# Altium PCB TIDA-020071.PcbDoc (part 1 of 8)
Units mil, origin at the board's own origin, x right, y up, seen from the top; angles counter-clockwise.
Board outline 5750 x 4050 mil, 6 copper layers (Top Layer, GND PLANE-1, SIGNAL LAYER, SIGNAL/POWER LAYER, GND PLANE-2, Bottom Layer), stack 59.616 mil thick; 776 components, 498 nets, 2205 pads, 871 vias.
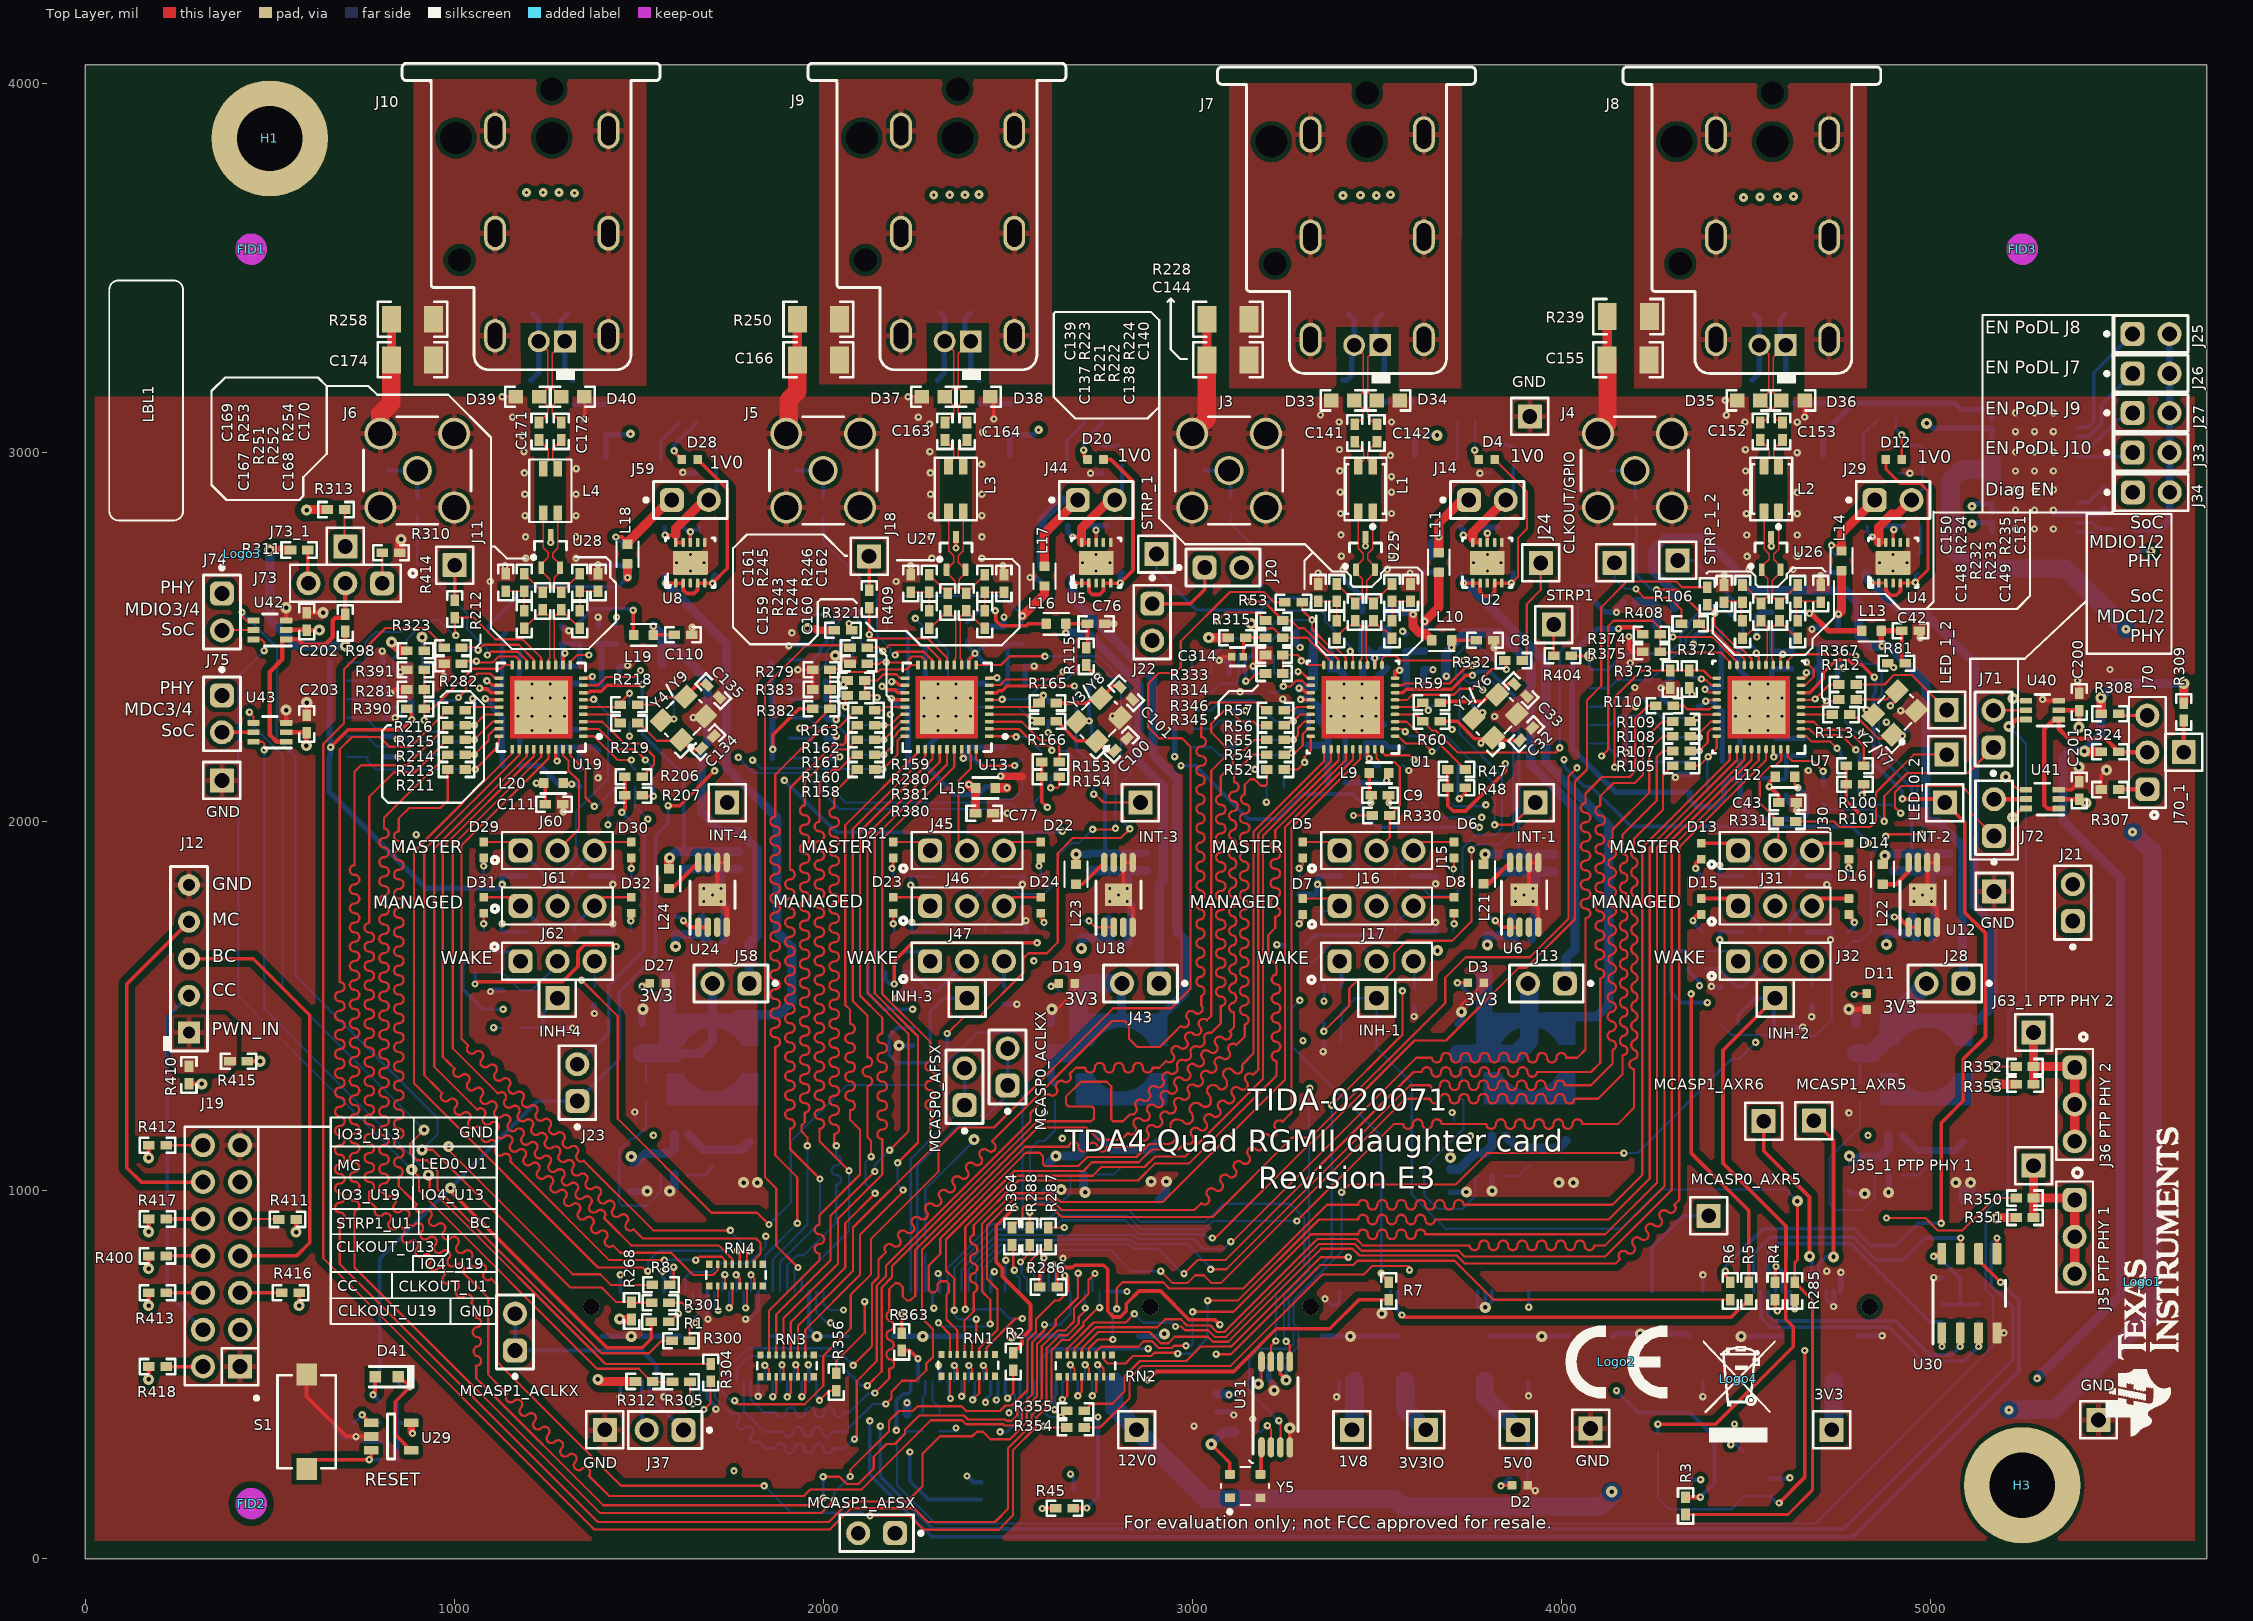
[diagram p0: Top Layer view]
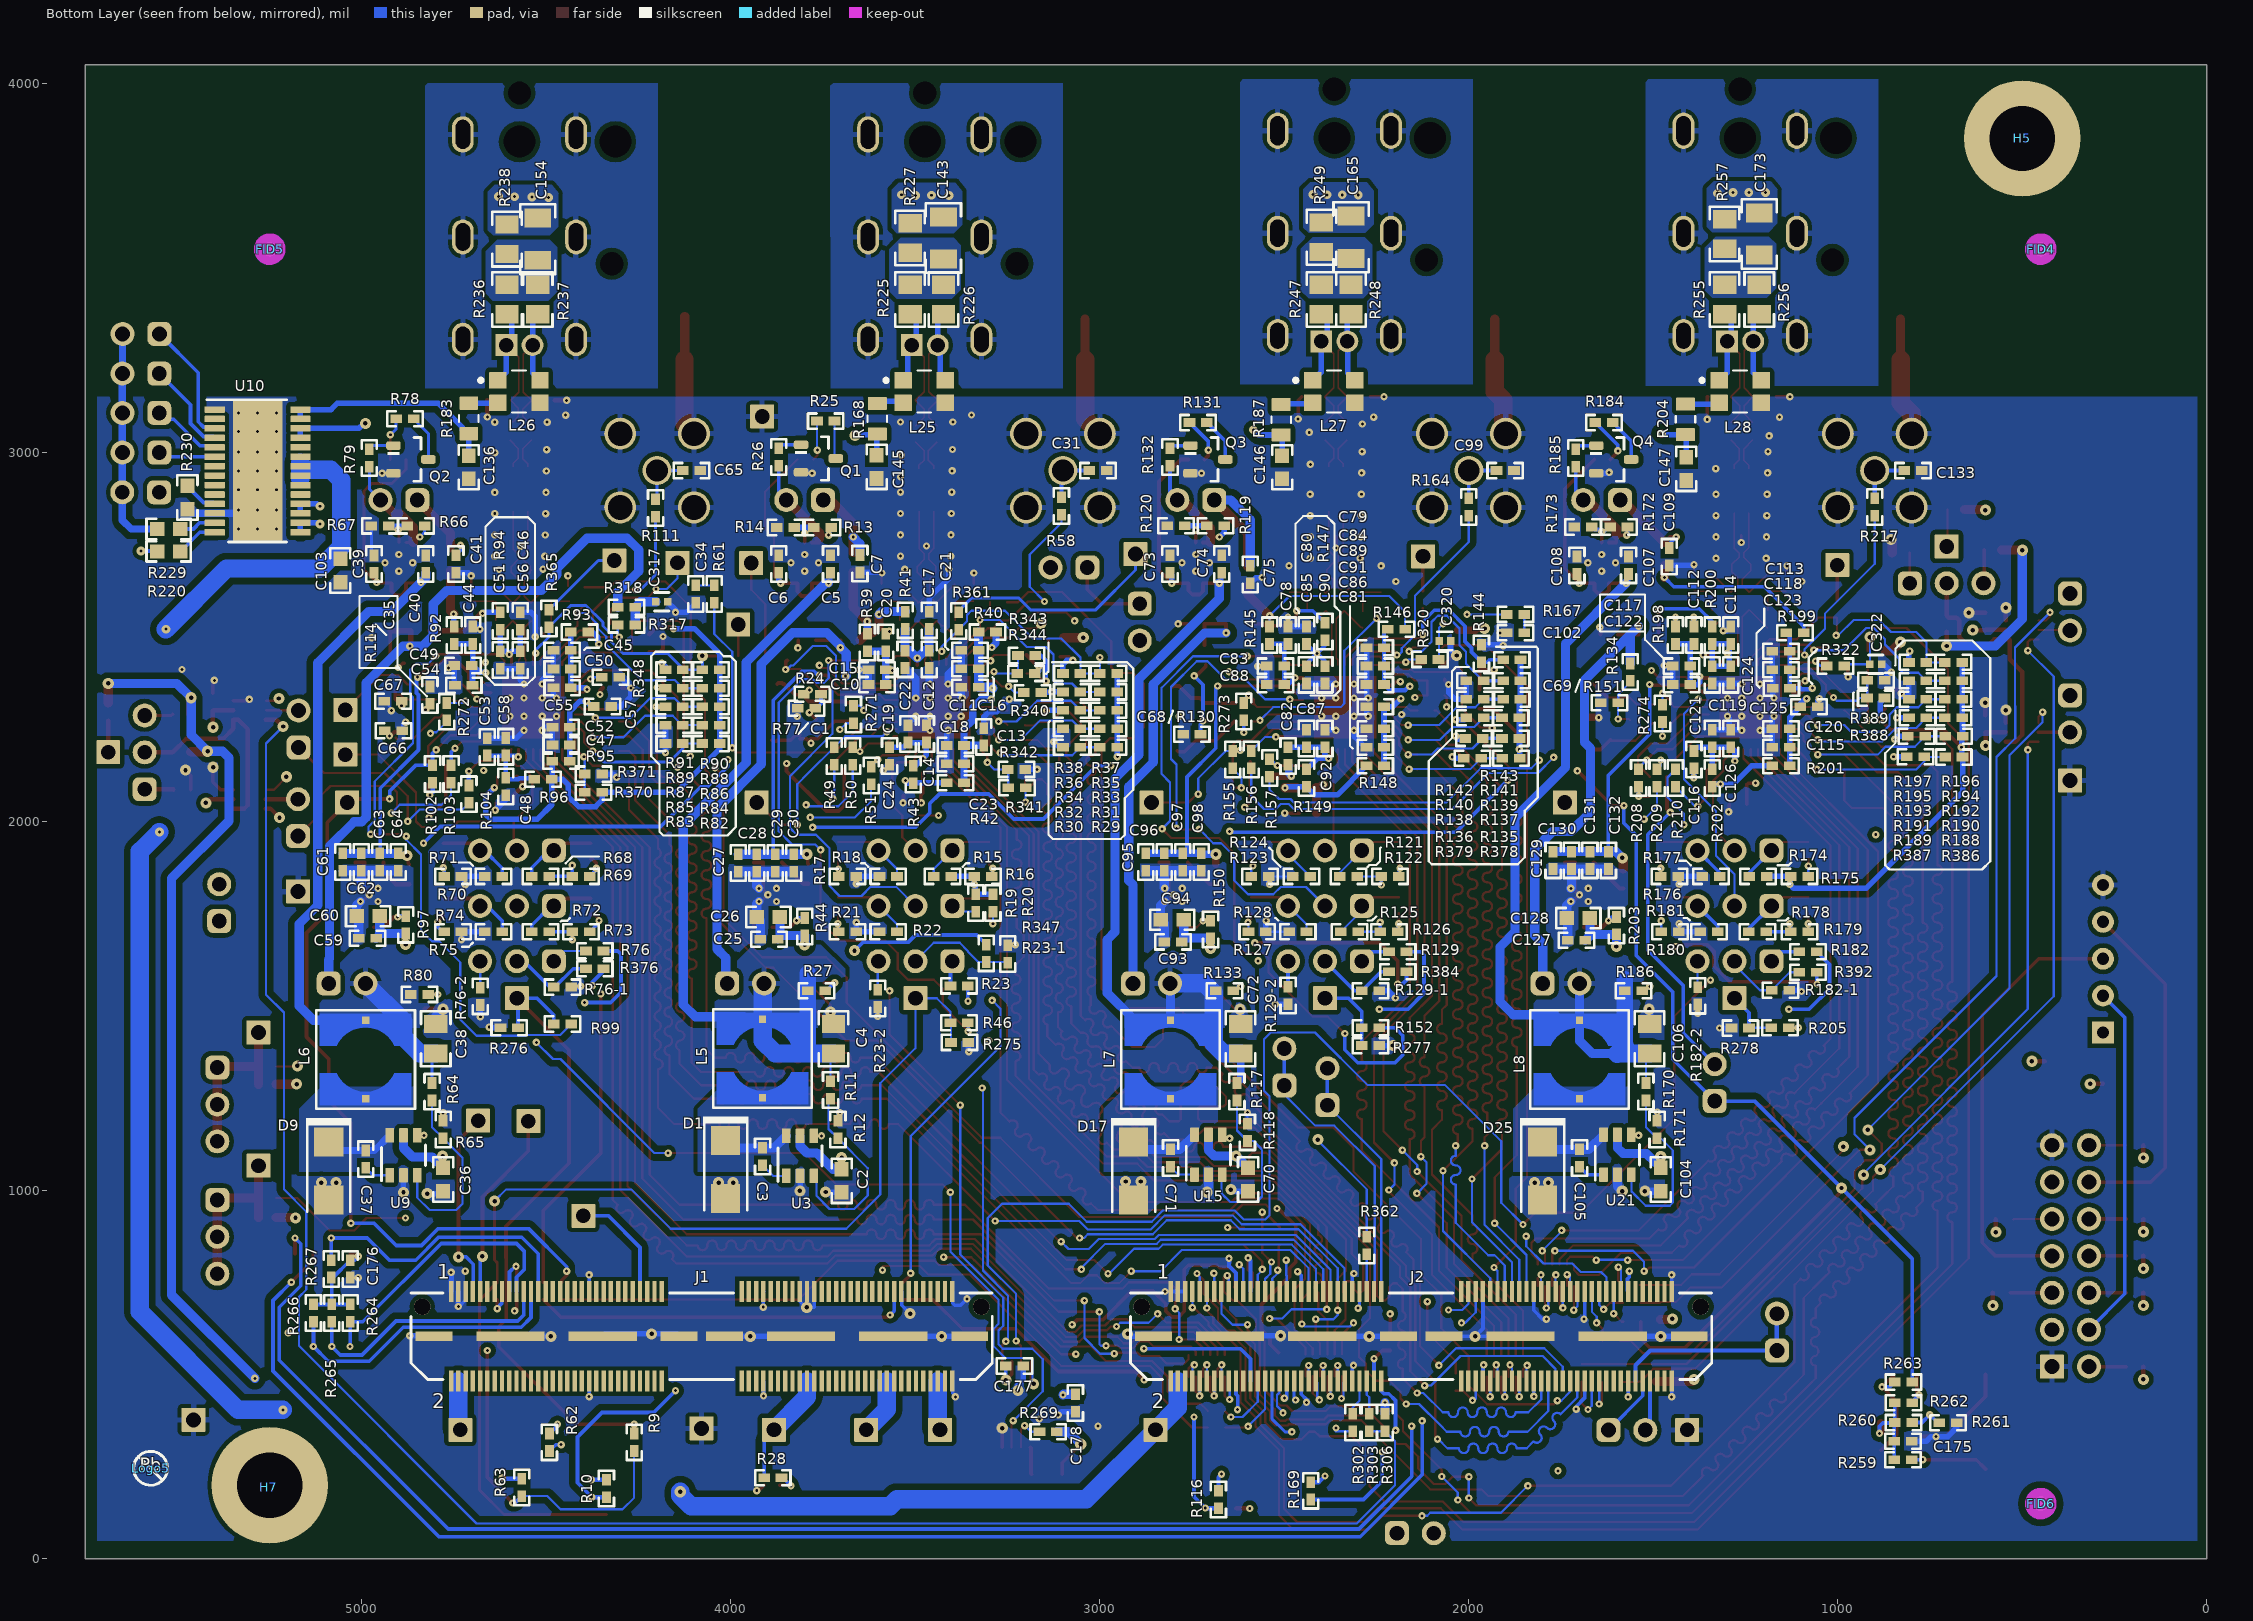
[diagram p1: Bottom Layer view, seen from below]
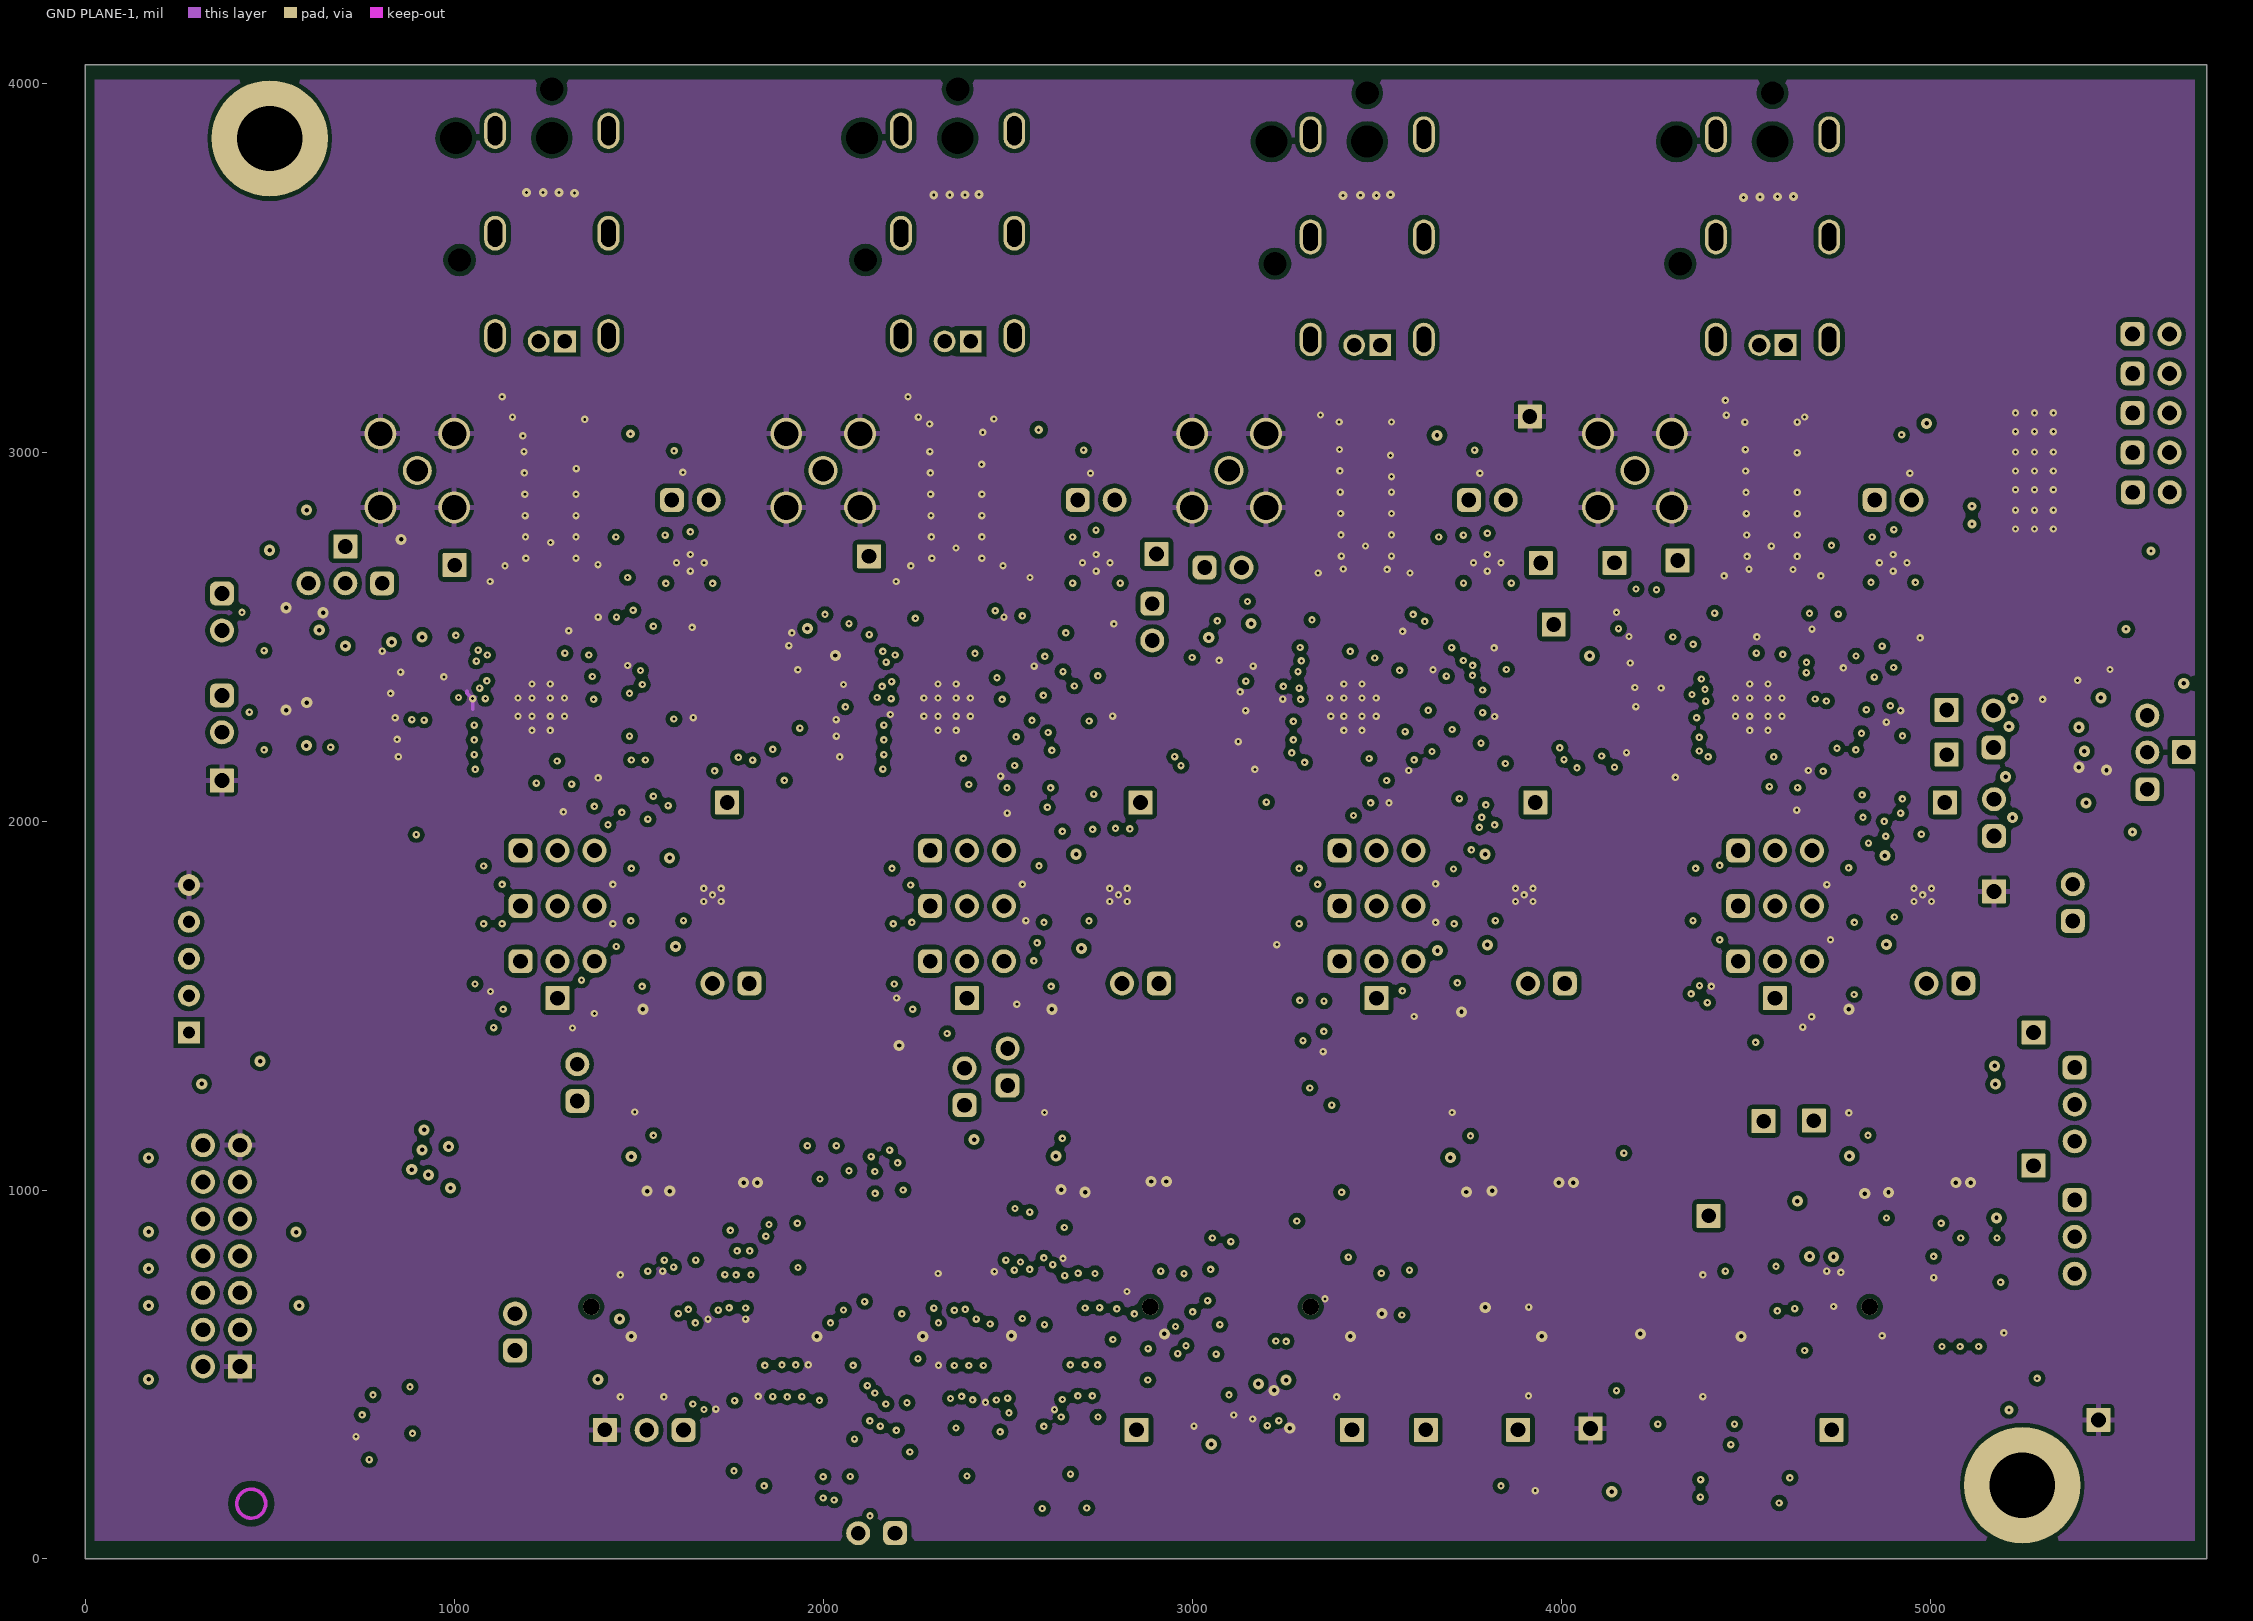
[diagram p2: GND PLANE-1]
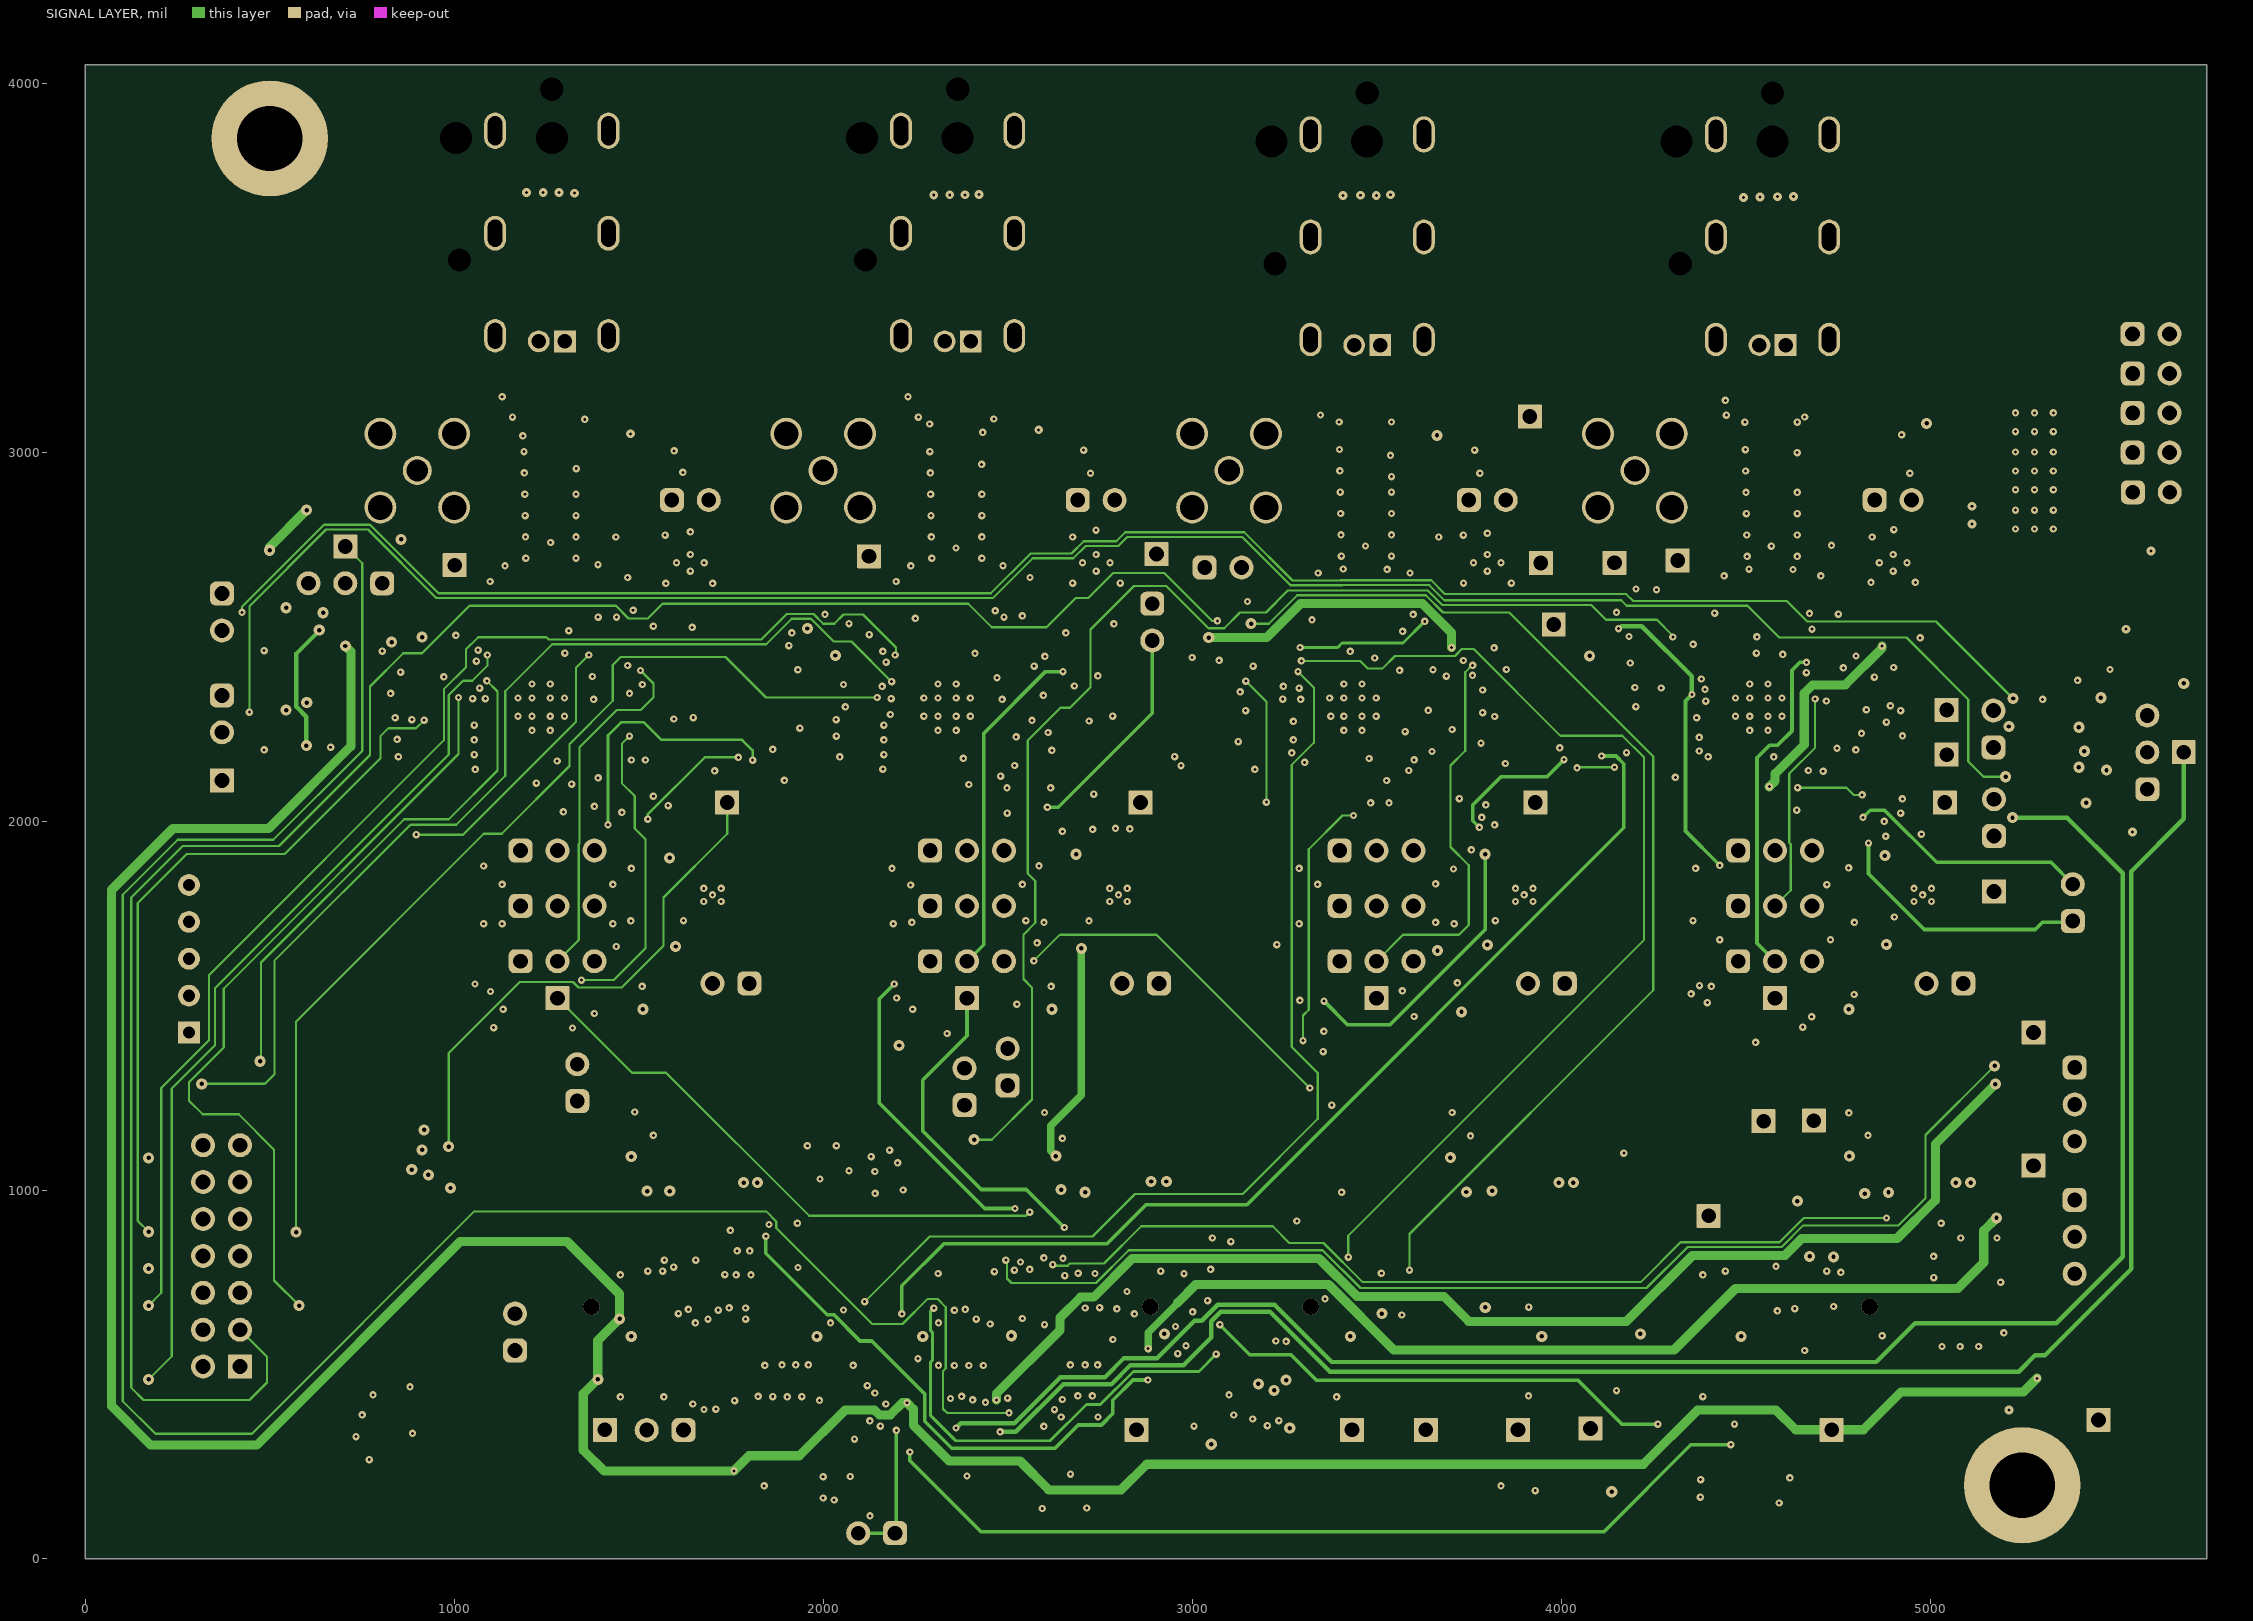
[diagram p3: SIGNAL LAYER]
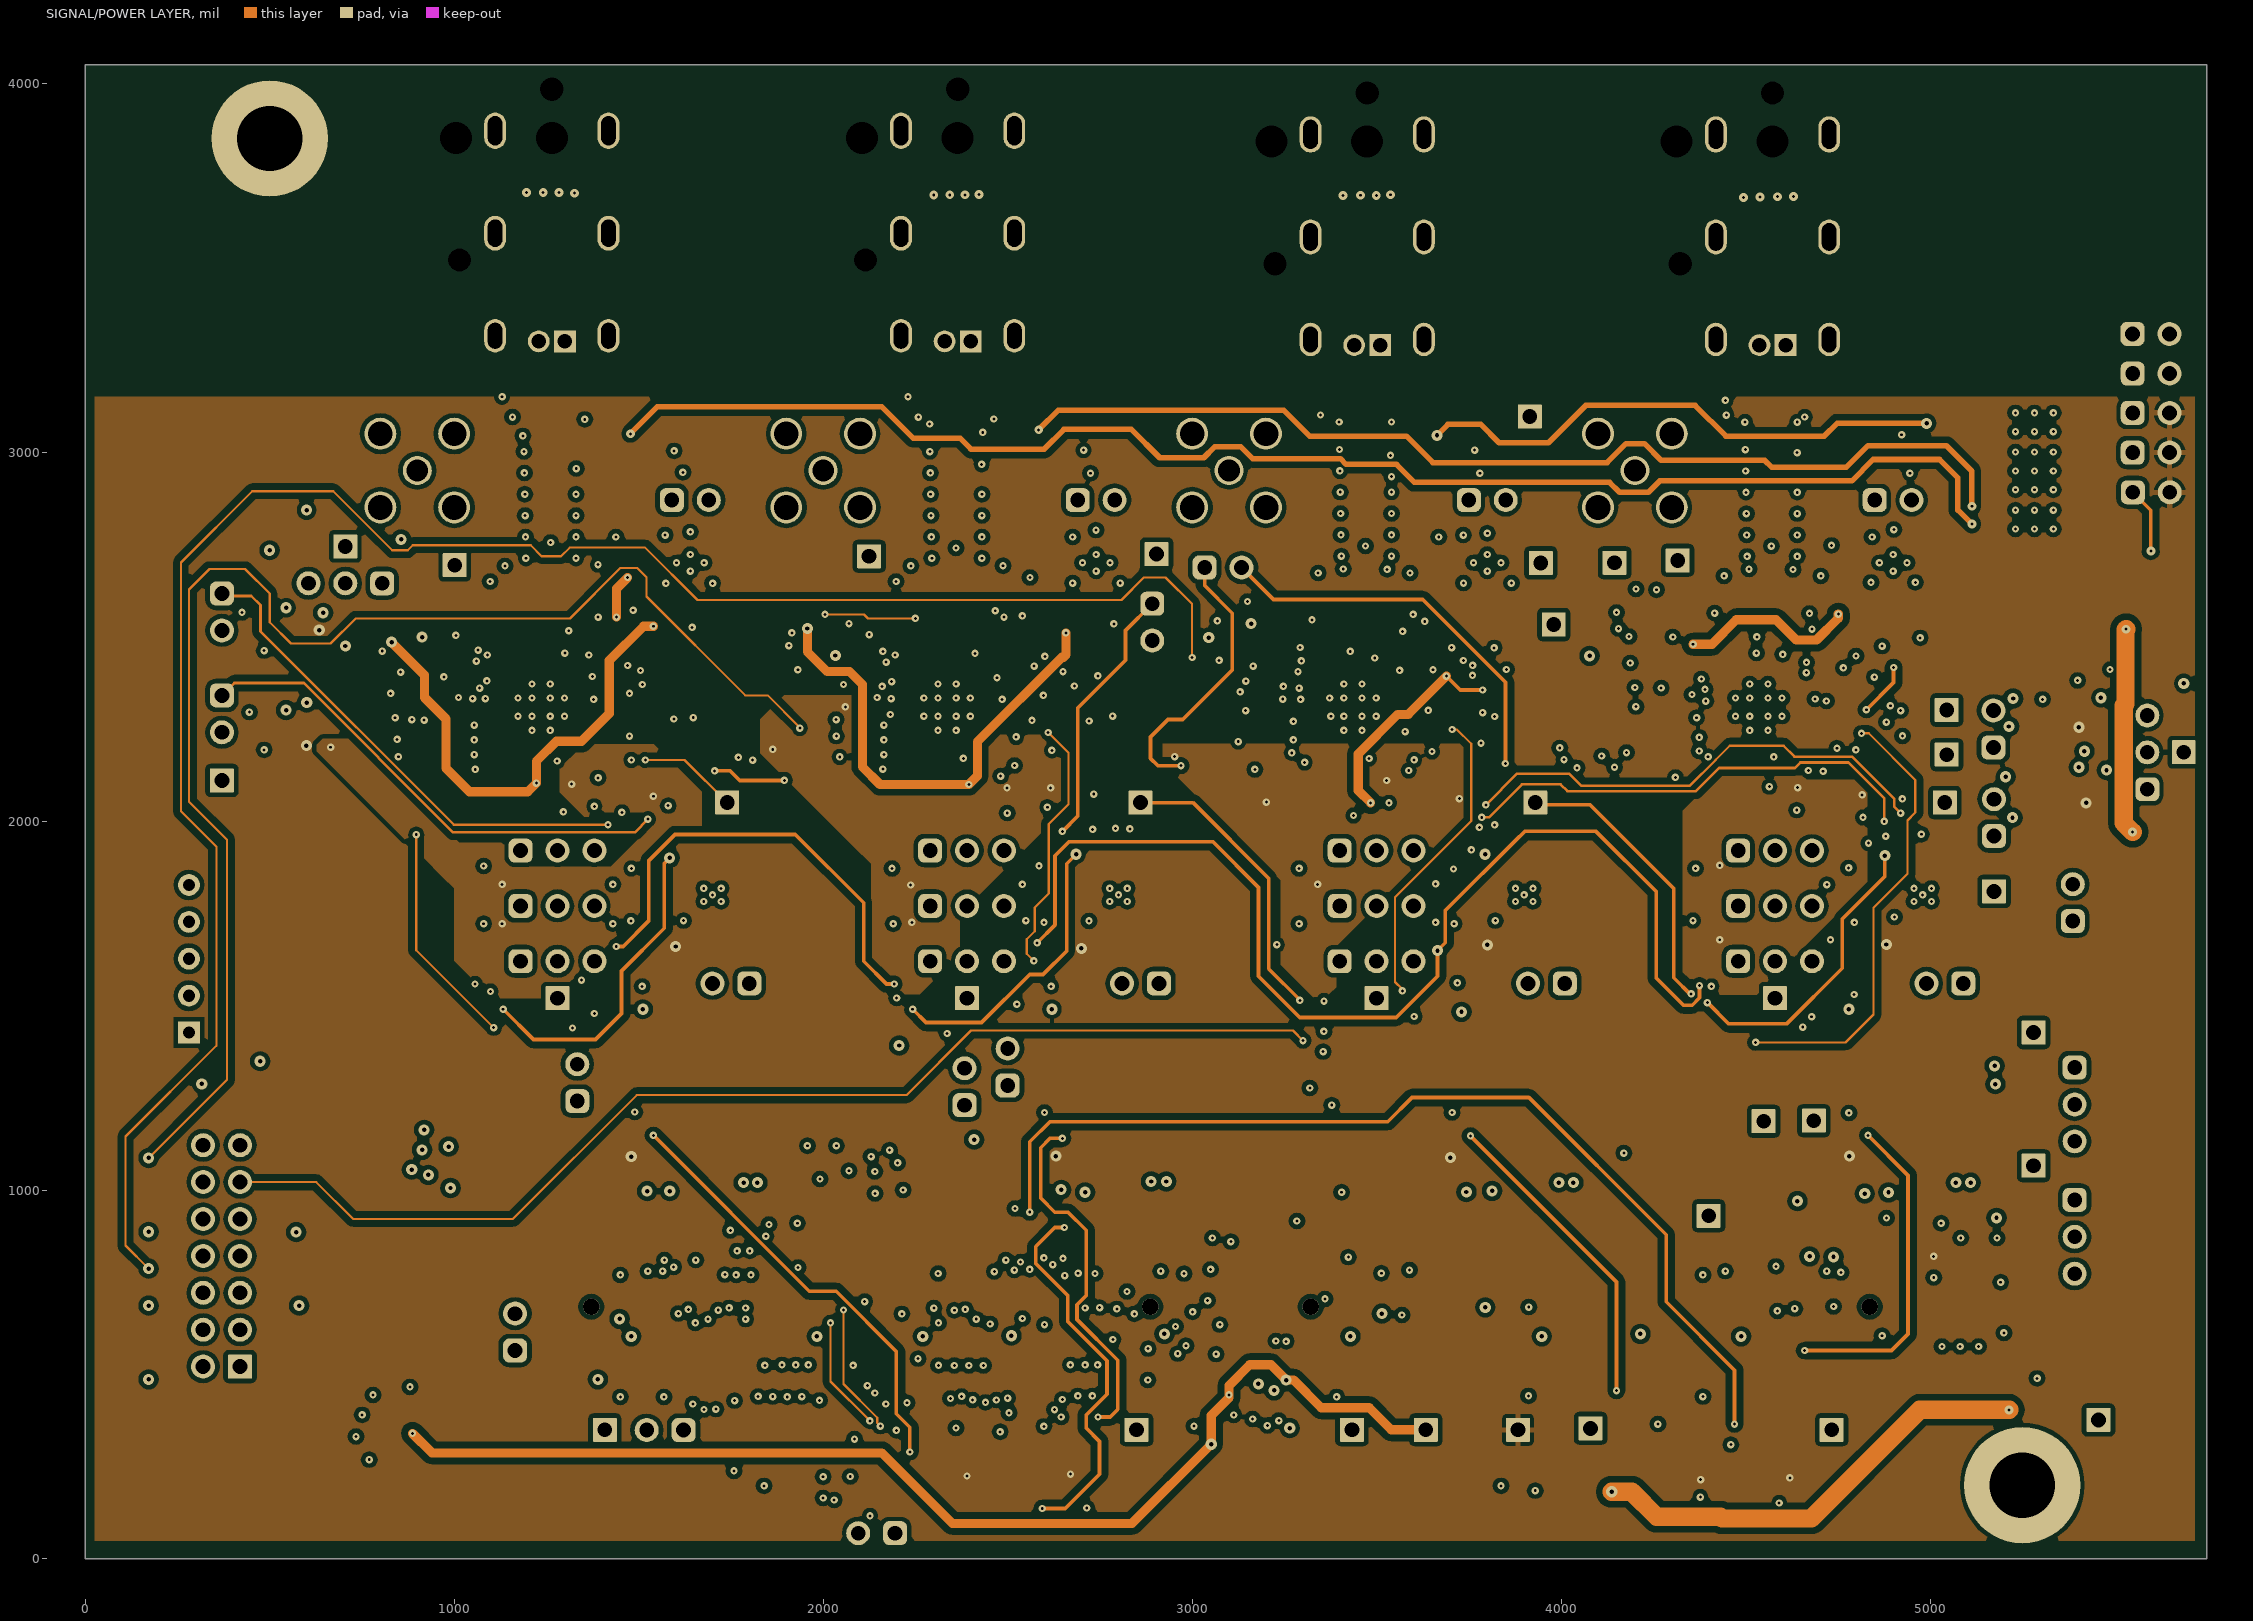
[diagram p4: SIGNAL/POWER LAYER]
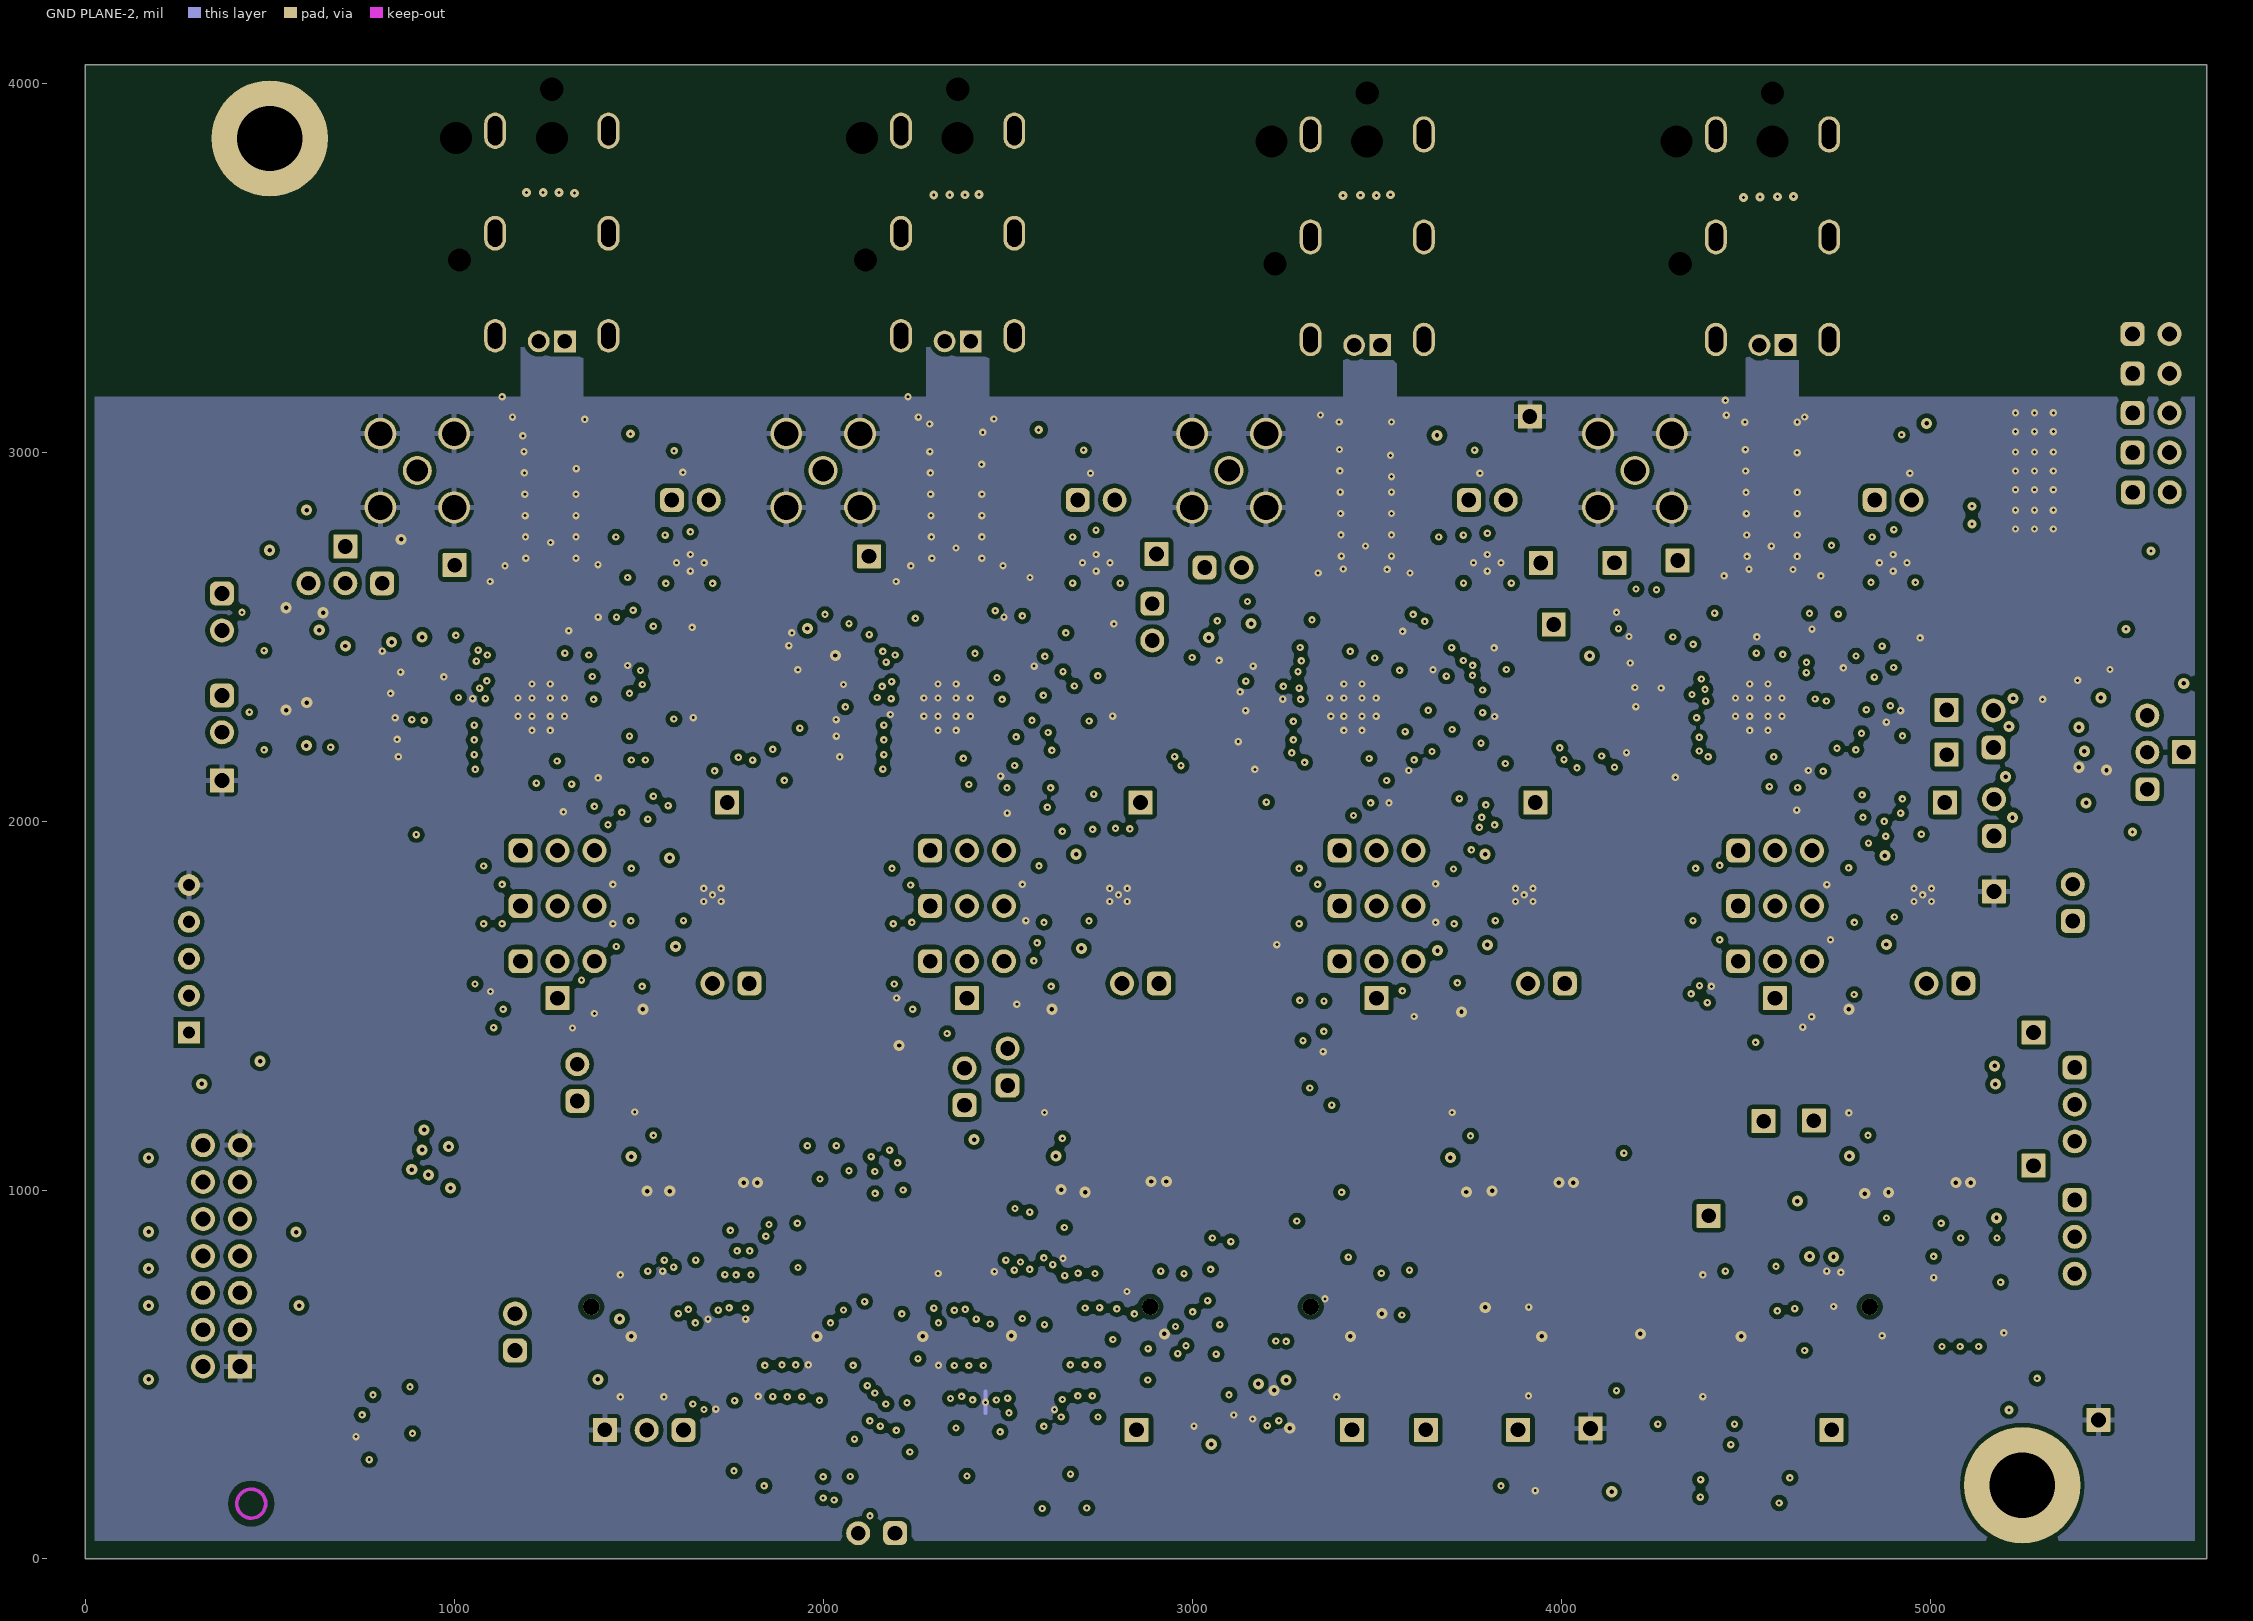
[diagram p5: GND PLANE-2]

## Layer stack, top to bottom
Top Solder: solder mask 0.4, Solder Resist, Dk 3.5
Top Layer: signal copper 1.4
Dielectric 1: prepreg 3.937, IT180A, Dk 4.1
GND PLANE-1: signal copper 1.4
Dielectric 2: core 5.906, IT180A, Dk 4.1
SIGNAL LAYER: signal copper 1.4
Dielectric 3: prepreg 31.496, IT180A, Dk 4.1
SIGNAL/POWER LAYER: signal copper 1.417
Dielectric 5: core 5.906, IT180A, Dk 4.1
GND PLANE-2: signal copper 1.417
Dielectric 4: prepreg 3.937, IT180A, Dk 4.1
Bottom Layer: signal copper 1.4
Bottom Solder: solder mask 0.4, Solder Resist, Dk 3.5

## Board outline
0,0 0,4050 5750,4050 5750,0

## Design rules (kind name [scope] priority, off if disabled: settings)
AcuteAngle [All] p1: minimum=4.50000000000000E+0001 checktracksonly=FALSE
AssemblyTestPointUsage [All] p1: valid=2
BoardOutlineClearance BoardOutlineClearance_MountingHoles [OnCopper and InComponentClass('Mounting Holes')] p1: gap=40 ignorepadtopadclearanceinfootprint=FALSE
BoardOutlineClearance BoardOutlineClearance_Poly [OnCopper and IsPoly] p2: gap=25 ignorepadtopadclearanceinfootprint=FALSE
BoardOutlineClearance [OnCopper and Not InComponentClass('Logo') and not InComponentClass('FiducialMark') and not InRegion(1000,500,4000,800) and not InPoly] p3: gap=75 ignorepadtopadclearanceinfootprint=FALSE except(30: SMDPad-OutlineEdge THPad-OutlineEdge THPad-CavityEdge THPad-CutoutEdge THPad-SplitBarrior THPad-SplitContinuation; 40: Track-OutlineEdge Track-CavityEdge Track-CutoutEdge Track-SplitBarrior Track-SplitContinuation Via-OutlineEdge Via-CavityEdge Via-CutoutEdge Via-SplitBarrior Via-SplitContinuation Fill-OutlineEdge Fill-CavityEdge Fill-CutoutEdge Fill-SplitBarrior Fill-SplitContinuation)
Clearance Clearance_Keepouts [((IsTrack Or IsArc) And Not InPoly) And IsFree and IsKeepOut vs ((IsTrack Or IsArc) And Not InPoly) And IsFree and IsKeepOut] p1: gap=0 ignorepadtopadclearanceinfootprint=FALSE
Clearance Clearance_Poly [InPolygon] p2: gap=12 ignorepadtopadclearanceinfootprint=FALSE except(18: Arc-Fill Arc-Poly Arc-Region Track-Fill Track-Poly Track-Region)
Clearance Clearance_FiducialMark [IsKeepOut and InComponentClass('FiducialMark') vs IsPad and InComponentClass('FiducialMark')] p3: gap=0 ignorepadtopadclearanceinfootprint=FALSE
Clearance [All] p4: gap=7 ignorepadtopadclearanceinfootprint=FALSE except(10: Arc-Hole Track-Hole Fill-Hole Poly-Hole Region-Hole)
ComponentClearance ComponentClearance_MountingHoles_FiducialMarks [InComponentClass('Mounting Holes') vs InComponentClass('FiducialMark')] p1: gap=50 collisioncheckmode=3 verticalgap=10 showdistances=FALSE
ComponentClearance ComponentClearance_Shunt [InComponentClass('Header') vs InComponentClass('Shunt')] p2: gap=0 collisioncheckmode=3 verticalgap=0 showdistances=FALSE
ComponentClearance ComponentClearance_Logo [InComponentClass('Logo')] p3: gap=50 collisioncheckmode=3 verticalgap=10 showdistances=FALSE
ComponentClearance ComponentClearance_ScrewToNut [(HasFootprint('NY PMS 440 0025 PH')) vs (HasFootprint('Keystone_1902C'))] p4: gap=0 collisioncheckmode=3 verticalgap=0 showdistances=FALSE
ComponentClearance ComponentClearance_MountingHoles [InComponentClass('Mounting Holes')] p5: gap=250 collisioncheckmode=3 verticalgap=100000 showdistances=FALSE
ComponentClearance ComponentClearance_SmallPassives [HasFootprint('0201*') or HasFootprint('0402*') or HasFootprint('0508') or HasFootprint('0603*') or HasFootprint('0612') or HasFootprint('0805*') or HasFootprint('0815*') or HasFootprint('0830*') or HasFootprint('1206*') or HasFootprint('1210*') or HasFootprint('1808*') or HasFootprint('1812*') or HasFootprint('1825*') or HasFootprint('2010*') or HasFootprint('2220*') or HasFootprint('2225*') or HasFootprint('2512*') or HasFootprint('2728*') or HasFootprint('3518*') vs HasFootprint('0201*') or HasFootprint('0402*') or HasFootprint('0508') or HasFootprint('0603*') or HasFootprint('0612') or HasFootprint('0805*') or HasFootprint('0815*') or HasFootprint('0830*') or HasFootprint('1206*') or HasFootprint('1210*') or HasFootprint('1808*') or HasFootprint('1812*') or HasFootprint('1825*') or HasFootprint('2010*') or HasFootprint('2220*') or HasFootprint('2225*') or HasFootprint('2512*') or HasFootprint('2728*') or HasFootprint('3518*')] p6: gap=14.96 collisioncheckmode=3 verticalgap=10 showdistances=FALSE
ComponentClearance ComponentClearance_THtoSMT [IsThruComponent vs IsSMTComponent] p7: gap=5 collisioncheckmode=3 verticalgap=5 showdistances=FALSE
ComponentClearance ComponentClearance_THtoTH [IsThruComponent vs IsThruComponent] p8: gap=4 collisioncheckmode=3 verticalgap=4 showdistances=FALSE
ComponentClearance [All] p9: gap=5 collisioncheckmode=3 verticalgap=5 showdistances=FALSE
DiffPairsRouting TRD [InDifferentialPairClass('TRD4')] p1: maxlimit=8 minlimit=8 mostfreqgap=8 toplayer_minwidth=4 toplayer_maxwidth=4 toplayer_prefwidth=4 midlayer1_minwidth=4 midlayer1_maxwidth=4 midlayer1_prefwidth=4 midlayer2_minwidth=4 midlayer2_maxwidth=4 midlayer2_prefwidth=4 midlayer3_minwidth=4 midlayer3_maxwidth=4 midlayer3_prefwidth=4 midlayer4_minwidth=4 midlayer4_maxwidth=4 midlayer4_prefwidth=4 bottomlayer_minwidth=4 bottomlayer_maxwidth=4 bottomlayer_prefwidth=4 maxuncoupledlength=500
DiffPairsRouting [All] p2: maxlimit=100 minlimit=8 mostfreqgap=10 toplayer_maxgap=20 toplayer_prefgap=8 toplayer_minwidth=4 toplayer_maxwidth=10 toplayer_prefwidth=4 midlayer1_mingap=10 midlayer1_minwidth=8 midlayer1_maxwidth=12 midlayer1_prefwidth=10 midlayer2_mingap=10 midlayer2_minwidth=8 midlayer2_maxwidth=12 midlayer2_prefwidth=10 midlayer3_mingap=10 midlayer3_minwidth=15 midlayer3_maxwidth=15 midlayer3_prefwidth=15 midlayer4_mingap=10 midlayer4_minwidth=15 midlayer4_maxwidth=15 midlayer4_prefwidth=15 bottomlayer_maxgap=20 bottomlayer_prefgap=8 bottomlayer_minwidth=4 bottomlayer_maxwidth=10 bottomlayer_prefwidth=4 maxuncoupledlength=1000
FabricationTestPointUsage TestPointUsage [All] p1: valid=2 allowmultiple=FALSE
FabricationTestpoint Testpoint [All] p1: side=3 testpointundercomponent=TRUE minsize=40 maxsize=100 preferedsize=60 minholesize=0 maxholesize=40 preferedholesize=32 testpointgrid=1 allowsidetop=TRUE allowsidebottom=TRUE usegrid=TRUE gridtolerance=0.01
FanoutControl Fanout_LCC [IsLCC] p1: bgadir=Out bgaviamode=Centered fanoutstyle=Auto fanoutdirection=Alternating viagrid=1 // Fanout_LCC (Default Rule)
FanoutControl Fanout_BGA [IsBGA] p2: bgadir=Out bgaviamode=Centered fanoutstyle=Auto fanoutdirection=Alternating viagrid=1 // Fanout_BGA (Default Rule)
FanoutControl Fanout_Default [All] p4: bgadir=Out bgaviamode=Centered fanoutstyle=Auto fanoutdirection=Alternating viagrid=1 // Fanout_Default (Default Rule)
FanoutControl Fanout_Small [(CompPinCount < 5)] p5: bgadir=Out bgaviamode=Centered fanoutstyle=Auto fanoutdirection=OutThenIn viagrid=1 // Fanout_Small (Default Rule)
HoleSize [All] p1: absolutevalues=TRUE maxlimit=251 minlimit=7.87 maxpercent=80.000 minpercent=20.000
MinimumAnnularRing MinimumAnnularRing_ThermalPadVias [IsVia and InAnyComponent] p1: minimumring=5.91
MinimumAnnularRing [All] p2: minimumring=5
MinimumSolderMaskSliver MinimumSolderMaskSliver_Logo [InComponentClass('Logo') vs InComponentClass('Logo')] p1: minsoldermaskwidth=0.7
MinimumSolderMaskSliver [All] p2: minsoldermaskwidth=3.7
PlaneClearance [All] p1: clearance=12
PlaneConnect [All] p1: planeconnectstyle=Direct reliefexpansion=10 reliefentries=4 reliefconductorwidth=10 reliefairgap=10
PolygonConnect PolygonConnect_1 [All] p1: thpad.connectstyle=Relief thpad.reliefconductorwidth=15 thpad.reliefentries=4 thpad.polygonreliefangle="90 Angle" thpad.airgapwidth=10 smdpad.connectstyle=Direct smdpad.reliefconductorwidth=10 smdpad.reliefentries=4 smdpad.polygonreliefangle="90 Angle" smdpad.airgapwidth=10 via.connectstyle=Direct via.reliefconductorwidth=10 via.reliefentries=4 via.polygonreliefangle="90 Angle" via.airgapwidth=10
PolygonConnect [All] p2: connectstyle=Direct reliefconductorwidth=10 reliefentries=4 polygonreliefangle="45 Angle" airgapwidth=10
RoutingVias ThermalPadVias [IsVia and InAnyComponent] p1: holewidth=7.87 width=19.68 viastyle="Through Hole" minholewidth=7.87 minwidth=19.68 maxholewidth=20 maxwidth=50
RoutingVias [All] p2: holewidth=12 width=30 viastyle="Through Hole" minholewidth=6 minwidth=18 maxholewidth=20 maxwidth=50
SilkToBoardRegionClearance [Not ((IsComment or IsDesignator) And (Hide <> 'False')) and not InRegion(1000,500,4000,800)] p1:
SilkToSilkClearance SilkToSilkClearance_Pb-FreeLogo [(HasFootprint('Pb-Free_Overlay_Medium') OR HasFootprint('Pb-Free_Overlay_Small')) vs (HasFootprint('Pb-Free_Overlay_Medium') OR HasFootprint('Pb-Free_Overlay_Small'))] p1: silktosilkclearance=0
SilkToSilkClearance [All] p2: silktosilkclearance=4
SilkToSolderMaskClearance SilkToComponentPadClearance [All] p1: minsilkscreentomaskgap=0 clearancetoexposedcopper=TRUE
SilkToSolderMaskClearance "Silk to Solder Mask Opening" [All] p2: minsilkscreentomaskgap=1 clearancetoexposedcopper=FALSE
SolderMaskExpansion [All] p1: expansion=1.97 istentingtop=FALSE
SupplyNets "Schematic Supply Nets_33" [InNet('+3V3-3')] p1: voltage=0.000
SupplyNets "Schematic Supply Nets_32" [InNet('+1V0_REG-4')] p2: voltage=0.000
SupplyNets "Schematic Supply Nets_31" [InNet('GND720-4')] p3: voltage=0.000
SupplyNets "Schematic Supply Nets_30" [InNet('Vpu-4')] p4: voltage=0.000
SupplyNets "Schematic Supply Nets_29" [InNet('+1V0-3')] p5: voltage=0.000
SupplyNets "Schematic Supply Nets_28" [InNet('+3V3_REG-4')] p6: voltage=0.000
SupplyNets "Schematic Supply Nets_27" [InNet('+3V3-4')] p7: voltage=0.000
SupplyNets "Schematic Supply Nets_26" [InNet('+3V3_REG-2')] p8: voltage=0.000
SupplyNets "Schematic Supply Nets_25" [InNet('3V3')] p9: voltage=0.000
SupplyNets "Schematic Supply Nets_24" [InNet('+1V1_REG-2')] p10: voltage=0.000
SupplyNets "Schematic Supply Nets_23" [InNet('GND')] p11: voltage=0.000
SupplyNets "Schematic Supply Nets_22" [InNet('1V8')] p12: voltage=0.000
SupplyNets "Schematic Supply Nets_21" [InNet('GND720-3')] p13: voltage=0.000
SupplyNets "Schematic Supply Nets_20" [InNet('GND720-1')] p14: voltage=0.000
SupplyNets "Schematic Supply Nets_19" [InNet('12V0')] p15: voltage=0.000
SupplyNets "Schematic Supply Nets_18" [InNet('+3V3-1')] p16: voltage=0.000
SupplyNets "Schematic Supply Nets_17" [InNet('+1V1_REG-1')] p17: voltage=0.000
SupplyNets "Schematic Supply Nets_16" [InNet('+1V1-2')] p18: voltage=0.000
SupplyNets "Schematic Supply Nets_15" [InNet('Vsleep3')] p19: voltage=0.000
SupplyNets "Schematic Supply Nets_14" [InNet('+1V1-1')] p20: voltage=0.000
SupplyNets "Schematic Supply Nets_13" [InNet('Vsleep4')] p21: voltage=0.000
SupplyNets "Schematic Supply Nets_12" [InNet('Vsleep1')] p22: voltage=0.000
SupplyNets "Schematic Supply Nets_11" [InNet('+1V0-4')] p23: voltage=0.000
SupplyNets "Schematic Supply Nets_10" [InNet('Vsleep2')] p24: voltage=0.000
SupplyNets "Schematic Supply Nets_9" [InNet('+3V3_REG-1')] p25: voltage=0.000
SupplyNets "Schematic Supply Nets_8" [InNet('3V3IO')] p26: voltage=0.000
SupplyNets "Schematic Supply Nets_7" [InNet('+1V0_REG-3')] p27: voltage=0.000
SupplyNets "Schematic Supply Nets_6" [InNet('5V0')] p28: voltage=0.000
SupplyNets "Schematic Supply Nets_5" [InNet('GND720-2')] p29: voltage=0.000
SupplyNets "Schematic Supply Nets_4" [InNet('+3V3_REG-3')] p30: voltage=0.000
SupplyNets "Schematic Supply Nets_3" [InNet('+3V3-2')] p31: voltage=0.000
SupplyNets "Schematic Supply Nets_2" [InNet('Vpu-2')] p32: voltage=0.000
SupplyNets "Schematic Supply Nets_1" [InNet('Vpu-3')] p33: voltage=0.000
SupplyNets "Schematic Supply Nets" [InNet('Vpu-1')] p34: voltage=0.000
Width rX1 [InNetClass('P0-R1-RD')and InNetClass('P0-R2-RD') and InNetClass('P1-R1-RD')and InNetClass('P1-R2-RD')and InNetClass('RX_D-1')] p1: maxlimit=11.4 minlimit=11.4 preferedwidth=11.4
Width [All] p2: maxlimit=100 minlimit=4 preferedwidth=10 checkconnectedcopper=TRUE
14 further rules are at their usual default settings.

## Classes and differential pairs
component class "AVB Headers": J11 J12 J18 J19 J24 R330 R332 R333 R400 R409 R410 R411 R412 R413 R414 R415 R416 R417 R418
component class MDIO_MUX: C200 C201 C202 C203 GND J70 J70_1 J71 J72 J73 J73_1 J74 J75 R98 R307 R308 R309 R310 R311 R313 R324 U40 U41 U42 U43
component class RESET: C175 D41 J20 J21 J22 J23 R259 R260 R261 R262 R263 S1 U29
component class Conn-TE-02: C167 C168 C169 C170 C171 C172 C173 C174 D39 D40 J10 L4 L28 R204 R251 R252 R253 R254 R255 R256 R257 R258 U28
component class Conn-TE-01: C159 C160 C161 C162 C163 C164 C165 C166 D37 D38 J9 L3 L27 R187 R243 R244 R245 R246 R247 R248 R249 R250 U27
component class Conn-Rb-02: C148 C149 C150 C151 C152 C153 C154 C155 D35 D36 J8 L2 L26 R183 R232 R233 R234 R235 R236 R237 R238 R239 U26
component class Conn-Rb-01: C137 C138 C139 C140 C141 C142 C143 C144 D33 D34 J7 L1 L25 R168 R221 R222 R223 R224 R225 R226 R227 R228 U25
component class "HSS and Memory": C103 C136 C145 C146 C147 C176 J25 J26 J27 J33 J34 R220 R229 R230 R264 R265 R266 R267 U10 U30
component class Header: 1V8 3V3 3V3IO 5V0 12V0 CLKOUT/GPIO GND INH-1 INH-2 INH-3 INH-4 INT-1 INT-2 INT-3 INT-4 J11 J12 J13 J14 J15 J16 J17 J18 J19 J20 J21 J22 J23 J24 J25 J26 J27 J28 J29 J30 J31 J32 J33 J34 "J35 PTP PHY 1" "J35_1 PTP PHY 1" "J36 PTP PHY 2" J37 J43 J44 J45 J46 J47 J58 J59 J60 J61 J62 "J63_1 PTP PHY 2" J70 J70_1 J71 J72 J73 J73_1 J74 J75 LED_0_2 LED_1_2 MCASP0_ACLKX MCASP0_AFSX MCASP0_AXR5 MCASP1_ACLKX MCASP1_AFSX MCASP1_AXR5 MCASP1_AXR6 STRP1 STRP_1 STRP_1_2
component class Connector: 1V8 3V3 3V3IO 5V0 12V0 GND J1 J2 "J35 PTP PHY 1" "J35_1 PTP PHY 1" "J36 PTP PHY 2" J37 "J63_1 PTP PHY 2" MCASP0_ACLKX MCASP0_AFSX MCASP0_AXR5 MCASP1_ACLKX MCASP1_AFSX MCASP1_AXR5 MCASP1_AXR6 R1 R2 R4 R5 R6 R7 R8 R268 R285 R286 R287 R288 R300 R301 R302 R303 R304 R305 R306 R312 R350 R351 R352 R353 R354 R355 R356 R362 R363 R364 RN1 RN2 RN3 RN4
component class CLOCK: C177 C178 R269 U31 Y5
component class 818-04: C69 C104 C105 C106 C107 C108 C109 C110 C111 C112 C113 C114 C115 C116 C117 C118 C119 C120 C121 C122 C123 C124 C125 C126 C127 C128 C129 C130 C131 C132 C133 C134 C135 C322 D25 D27 D28 D29 D30 D31 D32 INH-4 INT-4 J6 J58 J59 J60 J61 J62 L8 L18 L19 L20 L24 Q4 R62 R134 R151 R169 R170 R171 R172 R173 R174 R175 R176 R177 R178 R179 R180 R181 R182 R182-1 R182-2 R184 R185 R186 R188 R189 R190 R191 R192 R193 R194 R195 R196 R197 R198 R199 R200 R201 R202 R203 R205 R206 R207 R208 R209 R210 R211 R212 R213 R214 R215 R216 R217 R218 R219 R274 R278 R281 R282 R322 R323 R386 R387 R388 R389 R390 R391 R392 U8 U19 U21 U24 Y4 Y9
component class 818-03: C68 C70 C71 C72 C73 C74 C75 C76 C77 C78 C79 C80 C81 C82 C83 C84 C85 C86 C87 C88 C89 C90 C91 C92 C93 C94 C95 C96 C97 C98 C99 C100 C101 C102 C320 D17 D19 D20 D21 D22 D23 D24 INH-3 INT-3 J5 J43 J44 J45 J46 J47 L7 L15 L16 L17 L23 Q3 R45 R115 R116 R117 R118 R119 R120 R121 R122 R123 R124 R125 R126 R127 R128 R129 R129-1 R129-2 R130 R131 R132 R133 R135 R136 R137 R138 R139 R140 R141 R142 R143 R144 R145 R146 R147 R148 R149 R150 R152 R153 R154 R155 R156 R157 R158 R159 R160 R161 R162 R163 R164 R165 R166 R167 R273 R277 R279 R280 R320 R321 R378 R379 R380 R381 R382 R383 R384 U5 U13 U15 U18 Y3 Y8
component class 721-02: C35 C36 C37 C38 C39 C40 C41 C42 C43 C44 C45 C46 C47 C48 C49 C50 C51 C52 C53 C54 C55 C56 C57 C58 C59 C60 C61 C62 C63 C64 C65 C66 C67 C317 CLKOUT/GPIO D9 D11 D12 D13 D14 D15 D16 INH-2 INT-2 J4 J28 J29 J30 J31 J32 L6 L12 L13 L14 L22 LED_0_2 LED_1_2 Q2 R9 R63 R64 R65 R66 R67 R68 R69 R70 R71 R72 R73 R74 R75 R76 R76-1 R76-2 R78 R79 R80 R81 R82 R83 R84 R85 R86 R87 R88 R89 R90 R91 R92 R93 R94 R95 R96 R97 R99 R100 R101 R102 R103 R104 R105 R106 R107 R108 R109 R110 R111 R112 R113 R114 R272 R276 R317 R318 R331 R348 R365 R367 R370 R371 R372 R373 R374 R375 R376 R404 R408 STRP1 STRP_1_2 U4 U7 U9 U12 Y2 Y7
component class 721-01: C1 C2 C3 C4 C5 C6 C7 C8 C9 C10 C11 C12 C13 C14 C15 C16 C17 C18 C19 C20 C21 C22 C23 C24 C25 C26 C27 C28 C29 C30 C31 C32 C33 C34 C314 D1 D2 D3 D4 D5 D6 D7 D8 INH-1 INT-1 J3 J13 J14 J15 J16 J17 L5 L9 L10 L11 L21 Q1 R3 R10 R11 R12 R13 R14 R15 R16 R17 R18 R19 R20 R21 R22 R23 R23-1 R23-2 R24 R25 R26 R27 R28 R29 R30 R31 R32 R33 R34 R35 R36 R37 R38 R39 R40 R41 R42 R43 R44 R46 R47 R48 R49 R50 R51 R52 R53 R54 R55 R56 R57 R58 R59 R60 R61 R77 R271 R275 R314 R315 R340 R341 R342 R343 R344 R345 R346 R347 R361 STRP_1 U1 U2 U3 U6 Y1 Y6
component class "Mounting Holes": H1 H3
component class Logo: Logo1
component class Hardware: FID1 FID2 FID3 FID4 FID5 FID6 H1 H3 H5 H7 LBL1 Logo1 Logo2 Logo3 Logo4 Logo5 ZZ1 ZZ2 ZZ3 ZZ4
component class FiducialMark: FID1 FID2 FID3 FID4 FID5 FID6
component class AssemblyNote: ZZ1 ZZ2 ZZ3 ZZ4
component class Label: LBL1
differential pair TRD2B: +TRD2B_P -TRD2B_N
differential pair TRD1B: +TRD1B_P -TRD1B_N
differential pair TRD4: +TRD4_P -TRD4_N
differential pair TRD4C: +TRD4C_P -TRD4C_N
differential pair TRD4B: +TRD4B_P -TRD4B_N
differential pair TRD4A: +TRD4A_P -TRD4A_N
differential pair TRD3: +TRD3_P -TRD3_N
differential pair TRD3C: +TRD3C_P -TRD3C_N
differential pair TRD3B: +TRD3B_P -TRD3B_N
differential pair TRD3A: +TRD3A_P -TRD3A_N
differential pair TRD2: +TRD2_P -TRD2_N
differential pair TRD2C: +TRD2C_P -TRD2C_N
differential pair TRD2A: +TRD2A_P -TRD2A_N
differential pair TRD1: +TRD1_P -TRD1_N
differential pair TRD1C: +TRD1C_P -TRD1C_N
differential pair TRD1A: +TRD1A_P -TRD1A_N

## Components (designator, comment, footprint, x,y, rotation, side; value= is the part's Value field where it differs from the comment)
1V8 "TSW-101-07-G-S" TSW-101-07-G-S 3433.27,350 r0 top
3V3 "TSW-101-07-G-S" TSW-101-07-G-S 4733.27,350 r0 top
3V3IO "TSW-101-07-G-S" TSW-101-07-G-S 3633.27,350 r90 top
5V0 "TSW-101-07-G-S" TSW-101-07-G-S 3883.27,350 r0 top
12V0 "TSW-101-07-G-S" TSW-101-07-G-S 2849.32,350 r0 top
C1 "C1005X5R1H104K050BB" 0402 3795.29,2305.82 r0 bottom value=0.1uF
C2 "C1608X5R1V225K080AC" 0603 3700,1024.92 r270 bottom value=2.2uF
C3 "GRM155R61A154KE19D" 0402 3914.25,1090.53 r270 bottom value=0.15uF
C4 "C2012X5R1A476M125AC" 0805_HV 3721.65,1410 r90 bottom value=47uF
C5 "GRM155R61E105KA12D" 0402 3730,2696.38 r90 bottom value=1uF
C6 "GRM155R61E105KA12D" 0402 3870,2696.38 r90 bottom value=1uF
C7 "GRM155R61A106ME11" 0402 3650.35,2697.4 r270 bottom value=10uF
C8 "GRM155R61A106ME11" 0402 3793.62,2490 r0 top value=10uF
C9 "GRM155R61A106ME11" 0402 3508.74,2070 r0 top value=10uF
C10 "C1005X5R1E225K050BC" 0402 3603.62,2370 r0 bottom value=2.2uF
C11 "C1005X5R1E225K050BC" 0402 3351.91,2362.76 r0 bottom value=2.2uF
C12 "C1005X5R1E225K050BC" 0402 3462.66,2438.35 r270 bottom value=2.2uF
C13 "C1005X5R1E225K050BC" 0402 3314.41,2228.35 r90 bottom value=2.2uF
C14 "C1005X5R1E225K050BC" 0402 3470,2236.38 r90 bottom value=2.2uF
C15 "C1005X5R1H104K050BB" 0402 3603.62,2410 r0 bottom value=0.1uF
C16 "C1005X5R1H104K050BB" 0402 3351.91,2412.76 r0 bottom value=0.1uF
C17 "C1005X5R1H104K050BB" 0402 3462.66,2544 r90 bottom value=0.1uF
C18 "C1005X5R1H104K050BB" 0402 3391.73,2205 r0 bottom value=0.1uF
C19 "C1005X5R1H104K050BB" 0402 3520,2236.38 r90 bottom value=0.1uF
C20 "C0402C103J5RACTU" 0402 3580,2483.62 r90 bottom value=0.01uF
C21 "C0402C103J5RACTU" 0402 3351.91,2462.76 r0 bottom value=0.01uF
C22 "C0402C103J5RACTU" 0402 3528,2438.35 r270 bottom value=0.01uF
C23 "C0402C103J5RACTU" 0402 3391.73,2155 r0 bottom value=0.01uF
C24 "C0402C103J5RACTU" 0402 3570,2176.38 r270 bottom value=0.01uF
C25 "C1005X5R1H104K050BB" 0402 3896.38,1680 r0 bottom value=0.1uF
C26 "C1608X5R1E106M080AC" 0603 3898.5,1740 r0 bottom value=10uF
C27 "GRM155R61A106ME11" 0402 3980,1886.38 r270 bottom value=10uF
C28 "C1005X5R1H104K050BB" 0402 3930,1886.38 r270 bottom value=0.1uF
C29 "C0402C103J5RACTU" 0402 3880,1886.38 r270 bottom value=0.01uF
C30 "C0402C103J5RACTU" 0402 3830,1886.38 r270 bottom value=0.01uF
C31 "GRM1555C1H220FA01D" 0402 3005.51,2950 r180 bottom value=22pF
C32 "C0402C270J5GACTU" 0402 3905.71,2235.82 r45 top value=27pF
C33 "C0402C270J5GACTU" 0402 3890.78,2354.48 r315 top value=27pF
C34 "GRM1555C1H220FA01D" 0402 4095,2615 r270 bottom value=22pF
C35 "C1005X5R1H104K050BB" 0402 4815.74,2341.06 r90 bottom value=0.1uF
C36 "C1608X5R1V225K080AC" 0603 4780,1028.5 r270 bottom value=2.2uF
C37 "GRM155R61A154KE19D" 0402 4990,1083.62 r270 bottom value=0.15uF
C38 "C2012X5R1A476M125AC" 0805_HV 4800,1410 r90 bottom value=47uF
C39 "GRM155R61E105KA12D" 0402 4967.32,2696.14 r90 bottom value=1uF
C40 "GRM155R61E105KA12D" 0402 4827.32,2696.14 r90 bottom value=1uF
C41 "GRM155R61A106ME11" 0402 4745.13,2696.38 r270 bottom value=10uF
C42 "GRM155R61A106ME11" 0402 4946.93,2515.78 r0 top value=10uF
C43 "GRM155R61A106ME11" 0402 4613.62,2050 r0 top value=10uF
C44 "C1005X5R1E225K050BC" 0402 4700,2503.62 r90 bottom value=2.2uF
C45 "C1005X5R1E225K050BC" 0402 4457.24,2463.2 r0 bottom value=2.2uF
C46 "C1005X5R1E225K050BC" 0402 4571.23,2542.36 r90 bottom value=2.2uF
C47 "C1005X5R1E225K050BC" 0402 4460,2206.32 r0 bottom value=2.2uF
C48 "C1005X5R1E225K050BC" 0402 4610,2093.74 r270 bottom value=2.2uF
C49 "C1005X5R1H104K050BB" 0402 4726.37,2421.62 r0 bottom value=0.1uF
C50 "C1005X5R1H104K050BB" 0402 4457.24,2412.11 r0 bottom value=0.1uF
C51 "C1005X5R1H104K050BB" 0402 4625,2436.53 r270 bottom value=0.1uF
C52 "C1005X5R1H104K050BB" 0402 4460,2254.14 r0 bottom value=0.1uF
C53 "C1005X5R1H104K050BB" 0402 4660.55,2201.13 r90 bottom value=0.1uF
C54 "C0402C103J5RACTU" 0402 4723.99,2367.79 r0 bottom value=0.01uF
C55 "C0402C103J5RACTU" 0402 4457.24,2361.14 r0 bottom value=0.01uF
C56 "C0402C103J5RACTU" 0402 4571.23,2436.53 r270 bottom value=0.01uF
C57 "C0402C103J5RACTU" 0402 4348,2310.5 r180 bottom value=0.01uF
C58 "C0402C103J5RACTU" 0402 4610,2201.38 r90 bottom value=0.01uF
C59 "C1005X5R1H104K050BB" 0402 4985.24,1682.4 r0 bottom value=0.1uF
C60 "C1608X5R1E106M080AC" 0603 4983.11,1742.4 r0 bottom value=10uF
C61 "GRM155R61A106ME11" 0402 5051.61,1888.78 r270 bottom value=10uF
C62 "C1005X5R1H104K050BB" 0402 5001.61,1888.78 r270 bottom value=0.1uF
C63 "C0402C103J5RACTU" 0402 4951.61,1888.78 r270 bottom value=0.01uF
C64 "C0402C103J5RACTU" 0402 4901.61,1888.78 r270 bottom value=0.01uF
C65 "GRM1555C1H220FA01D" 0402 4107.09,2950 r180 bottom value=22pF
C66 "C0402C270J5GACTU" 0402 4914.49,2245 r180 bottom value=27pF
C67 "C0402C270J5GACTU" 0402 4915.87,2324.36 r0 bottom value=27pF
C68 "C1005X5R1H104K050BB" 0402 2750.8,2235.61 r0 bottom value=0.1uF
C69 "C1005X5R1H104K050BB" 0402 1618.73,2320.66 r0 bottom value=0.1uF
C70 "C1608X5R1V225K080AC" 0603 2598.49,1028.5 r270 bottom value=2.2uF
C71 "GRM155R61A154KE19D" 0402 2808.49,1086.38 r270 bottom value=0.15uF
C72 "C2012X5R1A476M125AC" 0805_HV 2618.49,1410 r90 bottom value=47uF
C73 "GRM155R61E105KA12D" 0402 2810,2696.38 r90 bottom value=1uF
C74 "GRM155R61E105KA12D" 0402 2670,2696.38 r90 bottom value=1uF
C75 "GRM155R61A106ME11" 0402 2592.54,2668.5 r270 bottom value=10uF
C76 "GRM155R61A106ME11" 0402 2739.95,2534.62 r0 top value=10uF
C77 "GRM155R61A106ME11" 0402 2436.58,2021.5 r0 top value=10uF
C78 "C1005X5R1E225K050BC" 0402 2490,2503.62 r90 bottom value=2.2uF
C79 "C1005X5R1E225K050BC" 0402 2253.62,2470 r0 bottom value=2.2uF
C80 "C1005X5R1E225K050BC" 0402 2440,2503.62 r90 bottom value=2.2uF
C81 "C1005X5R1E225K050BC" 0402 2253.62,2200 r0 bottom value=2.2uF
C82 "C1005X5R1E225K050BC" 0402 2490,2176.38 r270 bottom value=2.2uF
C83 "C1005X5R1H104K050BB" 0402 2523.62,2420 r0 bottom value=0.1uF
C84 "C1005X5R1H104K050BB" 0402 2253.62,2420 r0 bottom value=0.1uF
C85 "GRM155R61A474KE15D" 0402 2440,2396.38 r270 bottom value=0.47uF
C86 "GRM155R61A474KE15D" 0402 2253.62,2250 r0 bottom value=0.47uF
C87 "C1005X5R1H104K050BB" 0402 2440,2223.62 r90 bottom value=0.1uF
C88 "C0402C103J5RACTU" 0402 2523.62,2370 r0 bottom value=0.01uF
C89 "C0402C103J5RACTU" 0402 2253.62,2370 r0 bottom value=0.01uF
C90 "C0402C103J5RACTU" 0402 2390,2396.38 r270 bottom value=0.01uF
C91 "C0402C103J5RACTU" 0402 2253.62,2310 r0 bottom value=0.01uF
C92 "C0402C103J5RACTU" 0402 2390,2223.62 r90 bottom value=0.01uF
C93 "C1005X5R1H104K050BB" 0402 2801.89,1672.28 r0 bottom value=0.1uF
C94 "C1608X5R1E106M080AC" 0603 2804.02,1732.28 r0 bottom value=10uF
C95 "GRM155R61A106ME11" 0402 2875.51,1888.66 r270 bottom value=10uF
C96 "C1005X5R1H104K050BB" 0402 2825.51,1888.66 r270 bottom value=0.1uF
C97 "C0402C103J5RACTU" 0402 2775.51,1888.66 r270 bottom value=0.01uF
C98 "C0402C103J5RACTU" 0402 2725.51,1888.66 r270 bottom value=0.01uF
C99 "GRM1555C1H220FA01D" 0402 1901.38,2950 r180 bottom value=22pF
C100 "C0402C270J5GACTU" 0402 2807.2,2207.2 r45 top value=27pF
C101 "C0402C270J5GACTU" 0402 2821.55,2346.75 r315 top value=27pF
C102 "GRM1555C1H220FA01D" 0402 1873.62,2510 r0 bottom value=22pF
C103 "GCM188R71E104KA57D" 0603 5058.4,2678.84 r270 bottom value=0.1uF
C104 "C1608X5R1V225K080AC" 0603 1480,1028.5 r270 bottom value=2.2uF
C105 "GRM155R61A154KE19D" 0402 1700,1086.38 r270 bottom value=0.15uF
C106 "C2012X5R1A476M125AC" 0805_HV 1510,1410 r90 bottom value=47uF
C107 "GRM155R61E105KA12D" 0402 1567.11,2693.27 r90 bottom value=1uF
C108 "GRM155R61E105KA12D" 0402 1707.11,2693.27 r90 bottom value=1uF
C109 "GRM155R61A106ME11" 0402 1456.51,2716.38 r270 bottom value=10uF
C110 "GRM155R61A106ME11" 0402 1619.82,2504.62 r0 top value=10uF
C111 "GRM155R61A106ME11" 0402 1270.79,2045.2 r0 top value=10uF
C112 "C1005X5R1E225K050BC" 0402 1390,2503.62 r90 bottom value=2.2uF
C113 "C1005X5R1E225K050BC" 0402 1153.62,2460 r0 bottom value=2.2uF
C114 "C1005X5R1E225K050BC" 0402 1290,2503.62 r90 bottom value=2.2uF
C115 "C1005X5R1E225K050BC" 0402 1153.62,2200 r0 bottom value=2.2uF
C116 "C1005X5R1E225K050BC" 0402 1390,2166.38 r270 bottom value=2.2uF
C117 "C1005X5R1H104K050BB" 0402 1423.62,2420 r0 bottom value=0.1uF
C118 "C1005X5R1H104K050BB" 0402 1153.62,2410 r0 bottom value=0.1uF
C119 "GRM155R61A474KE15D" 0402 1340,2396.38 r270 bottom value=0.47uF
C120 "GRM155R61A474KE15D" 0402 1153.62,2250 r0 bottom value=0.47uF
C121 "C1005X5R1H104K050BB" 0402 1340,2223.62 r90 bottom value=0.1uF
C122 "C0402C103J5RACTU" 0402 1423.62,2370 r0 bottom value=0.01uF
C123 "C0402C103J5RACTU" 0402 1153.15,2360 r0 bottom value=0.01uF
C124 "C0402C103J5RACTU" 0402 1290,2396.38 r270 bottom value=0.01uF
C125 "C0402C103J5RACTU" 0402 1078,2310 r180 bottom value=0.01uF
C126 "C0402C103J5RACTU" 0402 1290,2223.62 r90 bottom value=0.01uF
C127 "C1005X5R1H104K050BB" 0402 1708.17,1677.16 r0 bottom value=0.1uF
C128 "C1608X5R1E106M080AC" 0603 1703.28,1737.16 r0 bottom value=10uF
C129 "GRM155R61A106ME11" 0402 1771.79,1893.54 r270 bottom value=10uF
C130 "C1005X5R1H104K050BB" 0402 1721.79,1893.54 r270 bottom value=0.1uF
C131 "C0402C103J5RACTU" 0402 1671.79,1893.54 r270 bottom value=0.01uF
C132 "C0402C103J5RACTU" 0402 1621.79,1893.54 r270 bottom value=0.01uF
C133 "GRM1555C1H220FA01D" 0402 796.06,2950 r180 bottom value=22pF
C134 "C0402C270J5GACTU" 0402 1686.78,2213.41 r45 top value=27pF
C135 "C0402C270J5GACTU" 0402 1701.94,2351.64 r315 top value=27pF
C136 "CGA3E1X7R1E105K080AD" 0603 4710.33,2958.99 r270 bottom value=1uF
C137 "GRM1555C1H220FA01D" 0402 3391.73,2518.9 r270 top value=22pF
C138 "GRM1555C1H220FA01D" 0402 3541.73,2518.9 r90 top value=22pF
C139 "GRM1555C1H470FA01D" 0402 3341.73,2618.9 r270 top value=47pF
C140 "GRM1555C1H470FA01D" 0402 3591.73,2618.9 r90 top value=47pF
C141 "GCM155R71H104KE02D" 0402 3440.87,3051.38 r270 top value=0.1uF
C142 "GCM155R71H104KE02D" 0402 3500.87,3051.38 r270 top value=0.1uF
C143 "GRM31BR73A472KW01L" 1206 3423.94,3580.42 r90 bottom value=4700pF
C144 "GRM31BR73A472KW01L" 1206 3097.09,3250 r180 top value=4700pF
C145 "CGA3E1X7R1E105K080AD" 0603 3605.08,2959.9 r270 bottom value=1uF
C146 "CGA3E1X7R1E105K080AD" 0603 2506.13,2958.7 r270 bottom value=1uF
C147 "CGA3E1X7R1E105K080AD" 0603 1410.77,2954.46 r270 bottom value=1uF
C148 "GRM1555C1H220FA01D" 0402 4491.73,2518.9 r270 top value=22pF
C149 "GRM1555C1H220FA01D" 0402 4641.73,2518.9 r90 top value=22pF
C150 "GRM1555C1H470FA01D" 0402 4441.73,2616.14 r270 top value=47pF
C151 "GRM1555C1H470FA01D" 0402 4703.94,2616.14 r90 top value=47pF
C152 "GCM155R71H104KE02D" 0402 4540,3056.38 r270 top value=0.1uF
C153 "GCM155R71H104KE02D" 0402 4600,3056.38 r270 top value=0.1uF
C154 "GRM31BR73A472KW01L" 1206 4523.48,3576.85 r90 bottom value=4700pF
C155 "GRM31BR73A472KW01L" 1206 4181.42,3250 r0 top value=4700pF
C159 "GRM1555C1H220FA01D" 0402 2287.64,2546.38 r270 top value=22pF
C160 "GRM1555C1H220FA01D" 0402 2437.64,2546.38 r90 top value=22pF
C161 "GRM1555C1H470FA01D" 0402 2237.64,2643.62 r270 top value=47pF
C162 "GRM1555C1H470FA01D" 0402 2490,2643.62 r90 top value=47pF
C163 "GCM155R71H104KE02D" 0402 2330,3056.38 r270 top value=0.1uF
C164 "GCM155R71H104KE02D" 0402 2390,3056.38 r270 top value=0.1uF
C165 "GRM31BR73A472KW01L" 1206 2319.11,3582.22 r90 bottom value=4700pF
C166 "GRM31BR73A472KW01L" 1206 1987.09,3250 r180 top value=4700pF
C167 "GRM1555C1H220FA01D" 0402 1190,2546.38 r270 top value=22pF
C168 "GRM1555C1H220FA01D" 0402 1340,2546.38 r270 top value=22pF
C169 "GRM1555C1H470FA01D" 0402 1140,2646.38 r270 top value=47pF
C170 "GRM1555C1H470FA01D" 0402 1389.92,2646.72 r90 top value=47pF
C171 "GCM155R71H104KE02D" 0402 1230,3056.38 r270 top value=0.1uF
C172 "GCM155R71H104KE02D" 0402 1290,3056.38 r270 top value=0.1uF
C173 "GRM31BR73A472KW01L" 1206 1212.98,3590.99 r90 bottom value=4700pF
C174 "GRM31BR73A472KW01L" 1206 887.09,3250 r180 top value=4700pF
C175 "C1005X5R1H104K050BB" 0402 823.62,319.09 r180 bottom value=0.1uF
C176 "GRM155R61E105KA12D" 0402 5031.5,786.38 r90 bottom value=1uF
C177 "C1005X5R1H104K050BB" 0402 3231.62,523.03 r180 bottom value=0.1uF
C178 "C1005X5R1H104K050BB" 0402 3066.15,423.09 r270 bottom value=0.1uF
C200 "C1005X5R1H104K050BB" 0402 5404.4,2322.93 r270 top value=0.1uF
C201 "C1005X5R1H104K050BB" 0402 5404.4,2082.52 r270 top value=0.1uF
C202 "C1005X5R1H104K050BB" 0402 600.45,2540.93 r270 top value=0.1uF
C203 "C1005X5R1H104K050BB" 0402 600.45,2263.01 r270 top value=0.1uF
C314 "C0402C473K8RACTU" FP-C0402-BB-MFG 3123,2445 r180 top value="47,000 pF"
C317 "C0402C473K8RACTU" FP-C0402-BB-MFG 4187.4,2594.25 r180 bottom value="47,000 pF"
C320 "C0402C473K8RACTU" FP-C0402-BB-MFG 2065,2488 r180 bottom value="47,000 pF"
C322 "C0402C473K8RACTU" FP-C0402-BB-MFG 897.24,2425 r180 bottom value="47,000 pF"
CLKOUT/GPIO "TSW-101-07-G-S" TSW-101-07-G-S 4144.88,2700 r90 top
D1 "B160-13-F" SMA 4014.12,1055.67 r270 bottom value=60V
D2 "150040GS73240" WL-SMCC_0402_Green 3888.35,200 r180 top value=Green
D3 "150040GS73240" WL-SMCC_0402_Green 3768.35,1561.65 r180 top value=Green
D4 "150040GS73240" WL-SMCC_0402_Green 3798.35,2980 r0 top value=Green
D5 "150040GS73240" WL-SMCC_0402_Green 3300,1921.65 r270 top value=Green
D6 "150040GS73240" WL-SMCC_0402_Green 3710,1921.65 r90 top value=Green
D7 "150040GS73240" WL-SMCC_0402_Green 3300,1768.35 r270 top value=Green
D8 "150040GS73240" WL-SMCC_0402_Green 3710,1771.65 r90 top value=Green
D9 "B160-13-F" SMA 5090,1051.26 r270 bottom value=60V
D11 "150040GS73240" WL-SMCC_0402_Green 4828.3,1511 r90 top value=Green
D12 "150040GS73240" WL-SMCC_0402_Green 4901.65,2980 r180 top value=Green
D13 "150040GS73240" WL-SMCC_0402_Green 4380,1918.35 r270 top value=Green
D14 "150040GS73240" WL-SMCC_0402_Green 4780,1918.35 r90 top value=Green
D15 "150040GS73240" WL-SMCC_0402_Green 4380,1768.35 r270 top value=Green
D16 "150040GS73240" WL-SMCC_0402_Green 4780,1768.35 r90 top value=Green
D17 "B160-13-F" SMA 2908.49,1051.26 r270 bottom value=60V
D19 "150040GS73240" WL-SMCC_0402_Green 2660.14,1560 r180 top value=Green
D20 "150040GS73240" WL-SMCC_0402_Green 2738.35,2980 r0 top value=Green
D21 "150040GS73240" WL-SMCC_0402_Green 2190,1921.65 r270 top value=Green
D22 "150040GS73240" WL-SMCC_0402_Green 2590,1921.65 r90 top value=Green
D23 "150040GS73240" WL-SMCC_0402_Green 2190,1771.65 r270 top value=Green
D24 "150040GS73240" WL-SMCC_0402_Green 2590,1771.65 r90 top value=Green
D25 "B160-13-F" SMA 1800,1051.26 r270 bottom value=60V
D27 "150040GS73240" WL-SMCC_0402_Green 1551.65,1560 r180 top value=Green
D28 "150040GS73240" WL-SMCC_0402_Green 1638.35,2980 r0 top value=Green
D29 "150040GS73240" WL-SMCC_0402_Green 1080,1921.65 r270 top value=Green
D30 "150040GS73240" WL-SMCC_0402_Green 1480,1921.65 r90 top value=Green
D31 "150040GS73240" WL-SMCC_0402_Green 1080,1771.65 r270 top value=Green
D32 "150040GS73240" WL-SMCC_0402_Green 1480,1771.65 r90 top value=Green
D33 "EZAEG3W11AV" 0603 3408.5,3140 r180 top
D34 "EZAEG3W11AV" 0603 3531.5,3140 r180 top
D35 "EZAEG3W11AV" 0603 4508.5,3140 r180 top
D36 "EZAEG3W11AV" 0603 4628.5,3140 r180 top
D37 "EZAEG3W11AV" 0603 2298.5,3150 r180 top
D38 "EZAEG3W11AV" 0603 2421.5,3150 r180 top
D39 "EZAEG3W11AV" 0603 1198.5,3150 r180 top
D40 "EZAEG3W11AV" 0603 1321.5,3150 r180 top
D41 "150060RS75000" WL-SMCW_RED 817.13,494.09 r180 top value=Red
FID1 "Fiducial" Fiducial10-20 450,3550 r0 top
FID2 "Fiducial" Fiducial10-20 450,150 r0 top
FID3 "Fiducial" Fiducial10-20 5250,3550 r0 top
FID4 "Fiducial" Fiducial10-20 450,3550 r180 bottom
FID5 "Fiducial" Fiducial10-20 5250,3550 r180 bottom
FID6 "Fiducial" Fiducial10-20 450,150 r180 bottom
GND "TSW-101-07-G-S" TSW-101-07-G-S 4079.97,354.01 r0 top
GND "TSW-101-07-G-S" TSW-101-07-G-S 5456.5,376.99 r0 top
GND "TSW-101-07-G-S" TSW-101-07-G-S 3915.27,3096.56 r0 top
GND "TSW-101-07-G-S" TSW-101-07-G-S 370.45,2110 r270 top
GND "TSW-101-07-G-S" TSW-101-07-G-S 1408.27,350 r0 top
GND "TSW-101-07-G-S" TSW-101-07-G-S 5173.35,1809.31 r270 top
H1 "NY PMS 440 0025 PH" "NY PMS 440 0025 PH"#1 500,3850 r0 top locked
H3 "NY PMS 440 0025 PH" "NY PMS 440 0025 PH"#2 5250,203.19 r0 top locked
H5 "1902C" Keystone_1902C 500,3850 r180 bottom locked
H7 "1902C" Keystone_1902C 5252.4,194.67 r180 bottom locked
INH-1 "TSW-101-07-G-S" TSW-101-07-G-S 3500,1520 r0 top
INH-2 "TSW-101-07-G-S" TSW-101-07-G-S 4580,1520 r90 top
INH-3 "TSW-101-07-G-S" TSW-101-07-G-S 2390,1520 r90 top
INH-4 "TSW-101-07-G-S" TSW-101-07-G-S 1280,1520 r90 top
INT-1 "TSW-101-07-G-S" TSW-101-07-G-S 3930,2050 r0 top
INT-2 "TSW-101-07-G-S" TSW-101-07-G-S 5040,2050 r90 top
INT-3 "TSW-101-07-G-S" TSW-101-07-G-S 2860,2050 r90 top
INT-4 "TSW-101-07-G-S" TSW-101-07-G-S 1740,2050 r90 top
J1 "QTH-060-01-L-D-A" SAMTEC_QTH-060-01-L-D-A 4079.13,603.5 r180 bottom
J2 "QTH-060-01-L-D-A" SAMTEC_QTH-060-01-L-D-A 2129.13,603.5 r180 bottom locked
J3 "901-144-8RFX" AMPHENOL_901-144-8RFX 3100,2950 r0 top
J4 "901-144-8RFX" AMPHENOL_901-144-8RFX 4200,2950 r0 top
J5 "901-144-8RFX" AMPHENOL_901-144-8RFX 2000,2950 r0 top
J6 "901-144-8RFX" AMPHENOL_901-144-8RFX 900,2950 r0 top
J7 "9-2304372-1" TE_1PORT_B1-B#1 3474.57,3973.07 r180 top locked
J8 "9-2304372-1" TE_1PORT_B1-B#1 4573.07,3973.07 r180 top locked
J9 "9-2304372-1" TE_1PORT_B1-B#2 2364.57,3983.07 r180 top locked
J10 "9-2304372-1" TE_1PORT_B1-B#2 1264.57,3983.07 r180 top locked
J11 "TSW-101-07-G-S" TSW-101-07-G-S 1001.47,2693.53 r90 top
J12 "800-10-005-10-001000" Mill-Max_800-10-005-10-001000 281.23,1626.78 r90 top
J13 "TSW-102-07-G-S" TSW-102-07-G-S 3960,1560 r180 top
J14 "TSW-102-07-G-S" TSW-102-07-G-S 3800,2870 r0 top
J15 "TSW-103-07-G-S" TSW-103-07-G-S 3500,1920 r0 top
J16 "TSW-103-07-G-S" TSW-103-07-G-S 3500,1770 r0 top
J17 "TSW-103-07-G-S" TSW-103-07-G-S 3500,1620 r0 top
J18 "TSW-101-07-G-S" TSW-101-07-G-S 2124.6,2717.61 r90 top
J19 "TSW-107-07-L-D-006" TSW-107-07-G-D 369.53,821.45 r90 top
J20 "TSW-102-07-G-S" TSW-102-07-G-S 3083.93,2687.13 r0 top
J21 "TSW-102-07-G-S" TSW-102-07-G-S 5386.85,1778.78 r90 top
J22 "TSW-102-07-G-S" TSW-102-07-G-S 2891.92,2539.03 r270 top
J23 "TSW-102-07-G-S" TSW-102-07-G-S 1333.7,1291 r90 top
J24 "TSW-101-07-G-S" TSW-101-07-G-S 3945.15,2699.6 r0 top
J25 "TSW-102-07-G-S" TSW-102-07-G-S 5598.71,3320.34 r0 top
J26 "TSW-102-07-G-S" TSW-102-07-G-S 5599.17,3212.72 r0 top
J27 "TSW-102-07-G-S" TSW-102-07-G-S 5599.21,3106.22 r0 top
J28 "TSW-102-07-G-S" TSW-102-07-G-S 5040,1560 r180 top
J29 "TSW-102-07-G-S" TSW-102-07-G-S 4900,2870 r0 top
J30 "TSW-103-07-G-S" TSW-103-07-G-S 4580,1920 r0 top
J31 "TSW-103-07-G-S" TSW-103-07-G-S 4580,1770 r0 top
J32 "TSW-103-07-G-S" TSW-103-07-G-S 4580,1620 r0 top
J33 "TSW-102-07-G-S" TSW-102-07-G-S 5599.21,2998.7 r0 top
J34 "TSW-102-07-G-S" TSW-102-07-G-S 5599.62,2890.97 r0 top
"J35 PTP PHY 1" "TSW-103-07-G-S" TSW-103-07-G-S 5391.85,873.23 r270 top
"J35_1 PTP PHY 1" "TSW-101-07-G-S" TSW-101-07-G-S 5280.47,1065.99 r270 top
"J36 PTP PHY 2" "TSW-103-07-G-S" TSW-103-07-G-S 5391.85,1231.9 r270 top
J37 "TSW-102-07-G-S" TSW-102-07-G-S 1571.82,349.26 r180 top
J43 "TSW-102-07-G-S" TSW-102-07-G-S 2860,1560 r180 top
J44 "TSW-102-07-G-S" TSW-102-07-G-S 2740,2870 r0 top
J45 "TSW-103-07-G-S" TSW-103-07-G-S 2390,1920 r0 top
J46 "TSW-103-07-G-S" TSW-103-07-G-S 2390,1770 r0 top
J47 "TSW-103-07-G-S" TSW-103-07-G-S 2390,1620 r0 top
J58 "TSW-102-07-G-S" TSW-102-07-G-S 1750,1560 r180 top
J59 "TSW-102-07-G-S" TSW-102-07-G-S 1640,2870 r0 top
J60 "TSW-103-07-G-S" TSW-103-07-G-S 1280,1920 r0 top
J61 "TSW-103-07-G-S" TSW-103-07-G-S 1280,1770 r0 top
J62 "TSW-103-07-G-S" TSW-103-07-G-S 1280,1620 r0 top
"J63_1 PTP PHY 2" "TSW-101-07-G-S" TSW-101-07-G-S 5280.47,1426.9 r270 top
J70 "TSW-103-07-G-S" TSW-103-07-G-S 5588.86,2186.22 r90 top
J70_1 "TSW-101-07-G-S" TSW-101-07-G-S 5687.51,2186.63 r90 top
J71 "TSW-102-07-G-S" TSW-102-07-G-S 5171.67,2249.31 r90 top
J72 "TSW-102-07-G-S" TSW-102-07-G-S 5173.35,2009.31 r90 top
J73 "TSW-103-07-G-S" TSW-103-07-G-S 705,2644.38 r180 top
J73_1 "TSW-101-07-G-S" TSW-101-07-G-S 705,2744.38 r180 top
J74 "TSW-102-07-G-S" TSW-102-07-G-S 370.45,2566.63 r270 top
J75 "TSW-102-07-G-S" TSW-102-07-G-S 370.45,2290.5 r270 top
L1 "DLW32MH101XT2" FP-DLW32MH101XT2_1210-MFG 3469.68,2899.96 r90 top
L2 "DLW32MH101XT2" FP-DLW32MH101XT2_1210-MFG 4569.69,2899.96 r90 top
L3 "DLW32MH201XK2" FP-DLW32MH201XK2_1210-MFG 2359.68,2899.96 r90 top
L4 "DLW32MH201XK2" FP-DLW32MH201XK2_1210-MFG 1260.83,2895.08 r90 top
L5 "744053150" WE-TPC-LH 3914.25,1356.3 r90 bottom value=15uH
L6 "744053150" WE-TPC-LH 4990,1353.7 r90 bottom value=15uH
L7 "744053150" WE-TPC-LH 2808.49,1353.7 r90 bottom value=15uH
L8 "744053150" WE-TPC-LH 1700,1353.7 r90 bottom value=15uH
L9 "BLM18HE102SN1D" FP-BLM18-0_15-t0_8-MFG 3506.57,2130 r0 top
L10 "BLM18KG601SH1" "FP-BLM18KG601SH1_0603 (1608 Metric)-MFG" 3676.57,2490 r180 top
L11 "BLM18KG601SH1" "FP-BLM18KG601SH1_0603 (1608 Metric)-MFG" 3668.38,2700.95 r270 top
L12 "BLM18HE102SN1D" FP-BLM18-0_15-t0_8-MFG 4606.57,2120 r0 top
L13 "BLM18KG601SH1" "FP-BLM18KG601SH1_0603 (1608 Metric)-MFG" 4841.29,2515.78 r180 top
L14 "BLM18KG601SH1" "FP-BLM18KG601SH1_0603 (1608 Metric)-MFG" 4760,2705.33 r270 top
L15 "BLM18HE102SN1D" FP-BLM18-0_15-t0_8-MFG 2440,2090 r0 top
L16 "BLM18KG601SH1" "FP-BLM18KG601SH1_0603 (1608 Metric)-MFG" 2631.43,2534.62 r180 top
L17 "BLM18KG601SH1" "FP-BLM18KG601SH1_0603 (1608 Metric)-MFG" 2600,2663.58 r270 top
L18 "BLM18KG601SH1" "FP-BLM18KG601SH1_0603 (1608 Metric)-MFG" 1469.69,2723.62 r270 top
L19 "BLM18KG601SH1" "FP-BLM18KG601SH1_0603 (1608 Metric)-MFG" 1513.43,2504.62 r180 top
L20 "BLM18HE102SN1D" FP-BLM18-0_15-t0_8-MFG 1269.05,2102.76 r0 top
L21 "BLM18KG102SH1D" FP-BLM18KG102SH1D_0603-MFG 3790,1856.57 r90 top
L22 "BLM18KG102SH1D" FP-BLM18KG102SH1D_0603-MFG 4871.61,1855.83 r90 top
L23 "BLM18KG102SH1D" FP-BLM18KG102SH1D_0603-MFG 2685.51,1855.71 r90 top
L24 "BLM18KG102SH1D" FP-BLM18KG102SH1D_0603-MFG 1581.79,1843.74 r90 top
L25 "ADL32VHR-3R9M" FP-ADL32VHR-3R9M_SMT_3MM2_2MM5-MFG 3476,3164 r180 bottom
L26 "ADL32VHR-3R9M" FP-ADL32VHR-3R9M_SMT_3MM2_2MM5-MFG 4574.5,3164 r180 bottom
L27 "ADL32VHR-3R9M" FP-ADL32VHR-3R9M_SMT_3MM2_2MM5-MFG 2366,3164 r180 bottom
L28 "ADL32VHR-3R9M" FP-ADL32VHR-3R9M_SMT_3MM2_2MM5-MFG 1264.57,3164 r180 bottom
LBL1 "THT-14-423-10" Label_650x200 165.27,3140.02 r90 top
LED_0_2 "TSW-101-07-G-S" TSW-101-07-G-S 5045,2180 r90 top
LED_1_2 "TSW-101-07-G-S" TSW-101-07-G-S 5045,2301 r90 top
Logo1 "Texas Instruments" TI_Stacked_Overlay_Small 5574.61,751.32 r90 top
Logo2 "CE Mark" CE_Mark_5mm 4150,534 r0 top
Logo3 "FCC disclaimer" FCC_disclaimer 425,2725 r90 top
Logo4 "WEEE logo" WEEE_Minimum 4480.44,488.81 r0 top
Logo5 "Pb-Free Symbol" Pb-Free_Overlay_Small 5572.82,245.88 r180 bottom
MCASP0_ACLKX "TSW-102-07-G-S" TSW-102-07-G-S 2500,1333.36 r90 top
MCASP0_AFSX "TSW-102-07-G-S" TSW-102-07-G-S 2383.42,1280 r90 top
MCASP0_AXR5 "TSW-101-07-G-S" TSW-101-07-G-S 4400,930 r90 top
MCASP1_ACLKX "TSW-102-07-G-S" TSW-102-07-G-S 1165,615 r90 top
MCASP1_AFSX "TSW-102-07-G-S" TSW-102-07-G-S 2145,70 r180 top
MCASP1_AXR5 "TSW-101-07-G-S" TSW-101-07-G-S 4685.04,1187.99 r90 top
MCASP1_AXR6 "TSW-101-07-G-S" TSW-101-07-G-S 4549,1186.51 r90 top
Q1 "BC847CLT1G" SOT-23 3762.76,2982.6 r180 bottom value="45 V"
Q2 "BC847CLT1G" SOT-23 4867.24,2980 r180 bottom value="45 V"
Q3 "BC847CLT1G" SOT-23 2707.24,2980 r180 bottom value="45 V"
Q4 "BC847CLT1G" SOT-23 1607.24,2980 r180 bottom value="45 V"
R1 "CRCW04020000Z0EDHP" 0402 1557.87,642.99 r180 top value=0
R2 "CRCW04020000Z0EDHP" 0402 2515,535 r90 top value=0
R3 "CRCW04020000Z0ED" 0402 4337.29,144.13 r90 top value=0
R4 "CRCW04020000Z0EDHP" 0402 4580,726.38 r270 top value=0
R5 "CRCW04020000Z0EDHP" 0402 4508.27,726.38 r90 top value=0
R6 "CRCW04020000Z0EDHP" 0402 4458.27,726.38 r90 top value=0
R7 "CRCW04020000Z0EDHP" 0402 3533.27,726.38 r90 top value=0
R8 "CRCW04020000Z0EDHP" 0402 1560.5,742.9 r180 top value=0
R9 "CRCW04020000Z0ED" 0402 4262.29,316.38 r270 bottom value=0
R10 "CRCW040210K0FKED" 0402 4337.29,191.38 r90 bottom value=10.0k
R11 "CRCW040233K2FKED" 0402 3730,1271.13 r90 bottom value=33.2k
R12 "CRCW040210K0FKED" 0402 3710,1163.62 r270 bottom value=10.0k
R13 "CRCW04025K60JNED" 0402 3751.98,2795.57 r180 bottom value=5.6k
R14 "CRCW040215K0FKED" 0402 3851.98,2795.57 r180 bottom value=15.0k
R15 "CRCW04022K49FKED" 0402 3426.38,1850 r180 bottom value=2.49k
R16 "CRCW04022K20JNED" 0402 3316.38,1850 r0 bottom value=2.2k
R17 "CRCW04022K20JNED" 0402 3683.62,1850 r180 bottom value=2.2k
R18 "CRCW04022K49FKED" 0402 3573.62,1850 r0 bottom value=2.49k
R19 "CRCW04022K49FKED" 0402 3336.54,1778.17 r90 bottom value=2.49k
R20 "CRCW04022K20JNED" 0402 3289.89,1778.17 r90 bottom value=2.2k
R21 "CRCW04022K20JNED" 0402 3683.62,1700 r180 bottom value=2.2k
R22 "CRCW04022K49FKED" 0402 3573.62,1700 r0 bottom value=2.49k
R23 "CRCW04022K20JNED" 0402 3381.38,1553.1 r0 bottom value=2.2k
R23-1 "CRCW040210K0FKED" 0402 3250,1639.88 r270 bottom value=10.0k
R23-2 "CRCW04022K20JNED" 0402 3601.93,1519.5 r270 bottom value=2.2k
R24 "ERJ-2GE0R00X" 0402 3779.4,2343.41 r180 bottom value=0
R25 "CRCW04022K20JNED" 0402 3743,3084 r0 bottom value=2.2k
R26 "CRCW04022K20JNED" 0402 3870,2986.38 r270 bottom value=2.2k
R27 "CRCW04022K20JNED" 0402 3768.15,1540 r0 bottom value=2.2k
R28 "CRCW04022K20JNED" 0402 3886.38,220 r0 bottom value=2.2k
R29 "CRCW04022K49FKED" 0402 2976.38,2200 r180 bottom value=2.49k
R30 "CRCW04022K49FKED" 0402 3076.38,2200 r180 bottom value=2.49k
R31 "CRCW04022K49FKED" 0402 2976.38,2250 r180 bottom value=2.49k
R32 "CRCW04022K49FKED" 0402 3076.38,2250 r180 bottom value=2.49k
R33 "CRCW04022K49FKED" 0402 2976.38,2300 r180 bottom value=2.49k
R34 "CRCW04022K49FKED" 0402 3076.38,2300 r180 bottom value=2.49k
R35 "CRCW04022K49FKED" 0402 2976.38,2350 r180 bottom value=2.49k
R36 "CRCW04022K49FKED" 0402 3076.38,2350 r180 bottom value=2.49k
R37 "CRCW04022K49FKED" 0402 2976.38,2400 r180 bottom value=2.49k
R38 "CRCW04022K49FKED" 0402 3076.38,2400 r180 bottom value=2.49k
R39 "CRCW04020000Z0EDHP" 0402 3630,2483.62 r90 bottom value=0
R40 "CRCW04020000Z0EDHP" 0402 3305,2512.28 r180 bottom value=0
R41 "CRCW04020000Z0EDHP" 0402 3527.28,2544 r90 bottom value=0
R42 "CRCW04020000Z0EDHP" 0402 3391.73,2103.62 r0 bottom value=0
R43 "CRCW04020000Z0EDHP" 0402 3505.62,2126.38 r270 bottom value=0
R44 "CRCW04020000Z0EDHP" 0402 3800,1713.62 r270 bottom value=0
R45 "CRCW04020000Z0ED" 0402 2654.11,137.61 r0 top value=0
R46 "CRCW04020000Z0EDHP" 0402 3381.38,1453.1 r0 bottom value=0
R47 "CRCW04020000Z0EDHP" 0402 3716.38,2140 r180 top value=0
R48 "CRCW04022K20JNED" 0402 3716.38,2090 r0 top value=2.2k
R49 "CRCW04022K20JNED" 0402 3720,2176.38 r270 bottom value=2.2k
R50 "CRCW04020000Z0EDHP" 0402 3670,2176.38 r270 bottom value=0
R51 "CRCW04020000Z0EDHP" 0402 3620,2123.62 r270 bottom value=0
R52 "CRCW04020000Z0EDHP" 0402 3226.38,2140 r180 top value=0
R53 "CRCW04020000Z0EDHP" 0402 3274.38,2592.91 r180 top value=0
R54 "CRCW04020000Z0EDHP" 0402 3226.38,2180 r180 top value=0
R55 "CRCW04020000Z0EDHP" 0402 3226.38,2220 r180 top value=0
R56 "CRCW04020000Z0EDHP" 0402 3226.38,2260 r180 top value=0
R57 "CRCW04020000Z0EDHP" 0402 3226.38,2300 r180 top value=0
R58 "ERJ-2GE0R00X" 0402 3104.13,2853.74 r90 bottom value=0
R59 "CRCW0402100RFKED" 0402 3648.62,2320.55 r180 top value=100
R60 "CRCW04021K00FKED" 0402 3648.62,2270.55 r180 top value=1.00k
R61 "CRCW04021K00FKED" 0402 4045,2615 r270 bottom value=1.00k
R62 "CRCW04020000Z0ED" 0402 4491.73,316.38 r270 bottom value=0
R63 "CRCW040210K0FKED" 0402 4566.73,194.13 r90 bottom value=10.0k
R64 "CRCW040233K2FKED" 0402 4810,1266.38 r90 bottom value=33.2k
R65 "CRCW040210K0FKED" 0402 4780,1163.62 r270 bottom value=10.0k
R66 "CRCW04025K60JNED" 0402 4853.7,2799.76 r180 bottom value=5.6k
R67 "CRCW040215K0FKED" 0402 4950.94,2799.76 r180 bottom value=15.0k
R68 "CRCW04022K49FKED" 0402 4516.38,1850 r180 bottom value=2.49k
R69 "CRCW04022K20JNED" 0402 4406.38,1850 r0 bottom value=2.2k
R70 "CRCW04022K20JNED" 0402 4753.62,1850 r180 bottom value=2.2k
R71 "CRCW04022K49FKED" 0402 4643.62,1850 r0 bottom value=2.49k
R72 "CRCW04022K49FKED" 0402 4516.38,1700 r180 bottom value=2.49k
R73 "CRCW04022K20JNED" 0402 4406.38,1700 r0 bottom value=2.2k
R74 "CRCW04022K20JNED" 0402 4753.62,1700 r180 bottom value=2.2k
R75 "CRCW04022K49FKED" 0402 4643.62,1700 r0 bottom value=2.49k
R76 "CRCW04022K20JNED" 0402 4368.98,1647.94 r0 bottom value=2.2k
R76-1 "CRCW040210K0FKED" 0402 4456.38,1550 r0 bottom value=10.0k
R76-2 "CRCW04022K20JNED" 0402 4679.2,1525 r270 bottom value=2.2k
R77 "ERJ-2GE0R00X" 0402 3795.29,2305.82 r0 bottom value=0
R78 "CRCW04022K20JNED" 0402 4883.62,3090 r0 bottom value=2.2k
R79 "CRCW04022K20JNED" 0402 4980,2983.62 r270 bottom value=2.2k
R80 "CRCW04022K20JNED" 0402 4843.62,1530 r0 bottom value=2.2k
R81 "ERJ-2GE0R00X" 0402 4909.01,2427.99 r180 top value=0
R82 "CRCW04022K49FKED" 0402 4053.62,2210 r180 bottom value=2.49k
R83 "CRCW04022K49FKED" 0402 4153.62,2210 r180 bottom value=2.49k
R84 "CRCW04022K49FKED" 0402 4053.62,2260 r180 bottom value=2.49k
R85 "CRCW04022K49FKED" 0402 4153.62,2260 r180 bottom value=2.49k
R86 "CRCW04022K49FKED" 0402 4053.62,2310 r180 bottom value=2.49k
R87 "CRCW04022K49FKED" 0402 4153.62,2310 r180 bottom value=2.49k
R88 "RC0402FR-0710KL" 0402 4053.62,2360 r180 bottom value=10.0k
R89 "CRCW04022K49FKED" 0402 4153.62,2360 r180 bottom value=2.49k
R90 "CRCW04022K49FKED" 0402 4053.62,2410 r180 bottom value=2.49k
R91 "CRCW04022K49FKED" 0402 4153.62,2410 r180 bottom value=2.49k
R92 "CRCW04020000Z0EDHP" 0402 4750,2503.62 r90 bottom value=0
R93 "CRCW04020000Z0EDHP" 0402 4410,2512.28 r180 bottom value=0
R94 "CRCW04020000Z0EDHP" 0402 4625,2542.36 r90 bottom value=0
R95 "CRCW04020000Z0EDHP" 0402 4460.87,2161.8 r0 bottom value=0
R96 "CRCW04020000Z0EDHP" 0402 4509.21,2113.63 r180 bottom value=0
R97 "CRCW04020000Z0EDHP" 0402 4881.61,1718.78 r270 bottom value=0
R98 "RG1005P-202-B-T5" 0402 705,2537.28 r90 top value=2.00k
R99 "CRCW04020000Z0EDHP" 0402 4456.38,1450 r0 bottom value=0
R100 "CRCW04020000Z0EDHP" 0402 4796.38,2150 r180 top value=0
R101 "CRCW04022K20JNED" 0402 4796.38,2100 r0 top value=2.2k
R102 "CRCW04022K20JNED" 0402 4808.54,2127.24 r270 bottom value=2.2k
R103 "CRCW04020000Z0EDHP" 0402 4758.35,2127.24 r270 bottom value=0
R104 "CRCW04020000Z0EDHP" 0402 4710,2072.75 r270 bottom value=0
R105 "CRCW04020000Z0EDHP" 0402 4326.38,2150 r180 top value=0
R106 "CRCW04020000Z0EDHP" 0402 4395.94,2610 r90 top value=0
R107 "CRCW04020000Z0EDHP" 0402 4326.38,2190 r180 top value=0
R108 "CRCW04020000Z0EDHP" 0402 4326.38,2230 r180 top value=0
R109 "CRCW04020000Z0EDHP" 0402 4326.38,2270 r180 top value=0
R110 "CRCW04020000Z0EDHP" 0402 4280.2,2312.5 r180 top value=0
R111 "ERJ-2GE0R00X" 0402 4204.13,2848.62 r90 bottom value=0
R112 "CRCW0402100RFKED" 0402 4776.37,2329.25 r180 top value=100
R113 "CRCW04021K00FKED" 0402 4758.19,2288.5 r180 top value=1.00k
R114 "ERJ-2GE0R00X" 0402 4815.74,2341.06 r90 bottom value=0
R115 "ERJ-2GE0R00X" 0402 2713.07,2446.56 r270 top value=0
R116 "CRCW040210K0FKED" 0402 2678.58,161.23 r90 bottom value=10.0k
R117 "CRCW040233K2FKED" 0402 2628.49,1266.38 r90 bottom value=33.2k
R118 "CRCW040210K0FKED" 0402 2600,1156.38 r270 bottom value=10.0k
R119 "CRCW04021K13FKED" 0402 2686.38,2800 r180 bottom value=1.13k
R120 "CRCW04024K53FKED" 0402 2793.62,2800 r180 bottom value=4.53k
R121 "CRCW04022K49FKED" 0402 2326.38,1850 r180 bottom value=2.49k
R122 "CRCW04022K20JNED" 0402 2213.62,1850 r0 bottom value=2.2k
R123 "CRCW04022K20JNED" 0402 2566.38,1850 r180 bottom value=2.2k
R124 "CRCW04022K49FKED" 0402 2453.62,1850 r0 bottom value=2.49k
R125 "CRCW04022K49FKED" 0402 2323.62,1700 r180 bottom value=2.49k
R126 "CRCW04022K20JNED" 0402 2216.38,1700 r0 bottom value=2.2k
R127 "CRCW04022K20JNED" 0402 2573.62,1700 r180 bottom value=2.2k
